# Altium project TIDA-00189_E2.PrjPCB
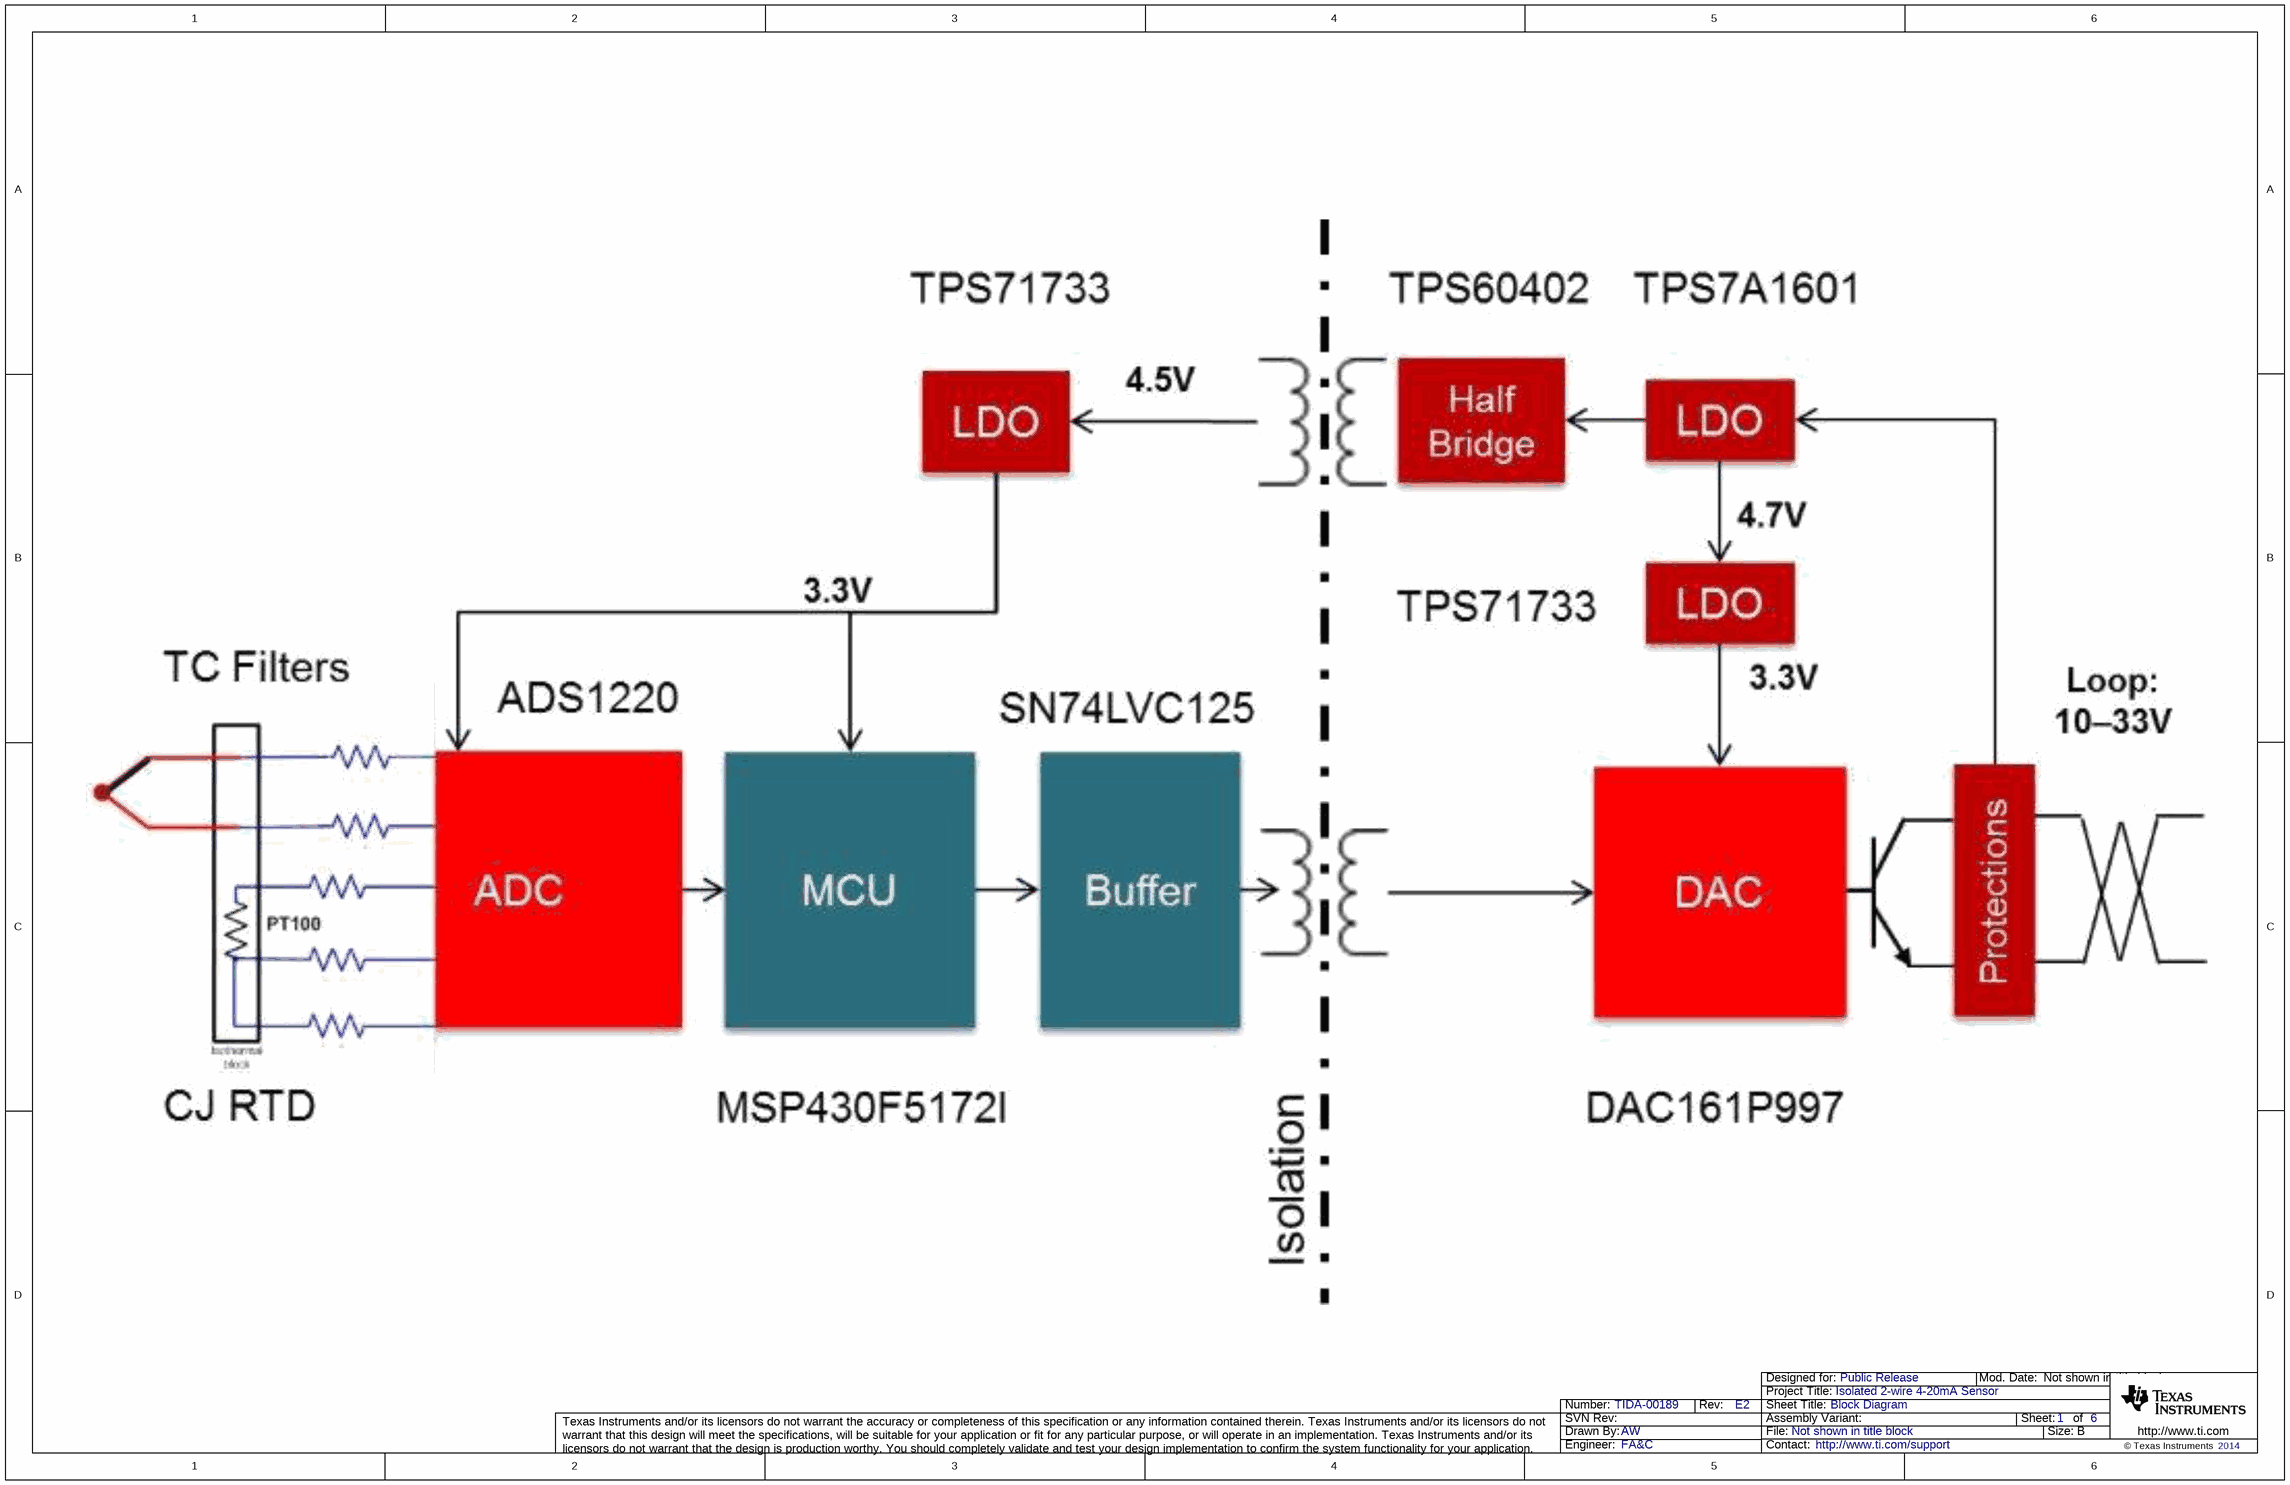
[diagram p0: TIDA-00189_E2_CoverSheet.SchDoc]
CopyrightYear: 2014; PCB_Layout: Jason M. Krypton Sol.; PCB_Rev: E1; PRJ_Customer: Public Release; PRJ_Engineer: FA&C; PRJ_Number: TIDA-00189; PRJ_Title: Isolated 2-wire 4-20mA Sensor; SCH_Rev: E2; TechSupport: http://www.ti.com/support
6 sheets, 164 parts. Net scope: global (net labels, ports and power ports of the same name join across sheets).
Board file: TIDA-00189_E2.PcbDoc
Sheets:
  TIDA-00189_E2_CoverSheet.SchDoc
  TIDA-00189_E2_Hardware.SchDoc
  TIDA-00189_E2_PWR.SchDoc
  TIDA-00189_E2_DAC.SchDoc
  TIDA-00189_E2_AFE_MCU.SchDoc
  TIDA-00189_E2_Periph.SchDoc

## Sheet TIDA-00189_E2_CoverSheet.SchDoc: Block Diagram
size 431 x 279 mm; Date: Not shown in title block; ApprovedBy: Not shown in title block; CheckedBy: Not shown in title block; Author: Not shown in title block; CompanyName: Not shown in title block; DrawnBy: AW; Engineer: Not shown in title block; Organization: Not shown in title block; Address1: Not shown in title block; Address2: Not shown in title block; Address3: Not shown in title block; Address4: Not shown in title block; DocumentNumber: 1; Revision: Use project parameter SCH_Rev; SheetNumber: 1; SheetTotal: 6; PageSetup: Record=PageOptions|CenterHorizontal=True|CenterVertical=True|PrintScale=1.00|XCorrection=1.00|YCorrection=1.00|PrintKind=0|BorderSize=5000000|LeftOffset=0|BottomOffset=0|Orientation=2|PaperLength=1000|PaperWidth=1000|Scale=100|PaperSource=15|PrintQuality=600|MediaType=1|DitherType=10|PaperKind=Letter|PrintScaleMode=1

## Sheet TIDA-00189_E2_Hardware.SchDoc: Hardware
size 431 x 279 mm; Date: Not shown in title block; ApprovedBy: Not shown in title block; CheckedBy: Not shown in title block; Author: Not shown in title block; CompanyName: Not shown in title block; DrawnBy: AW; Engineer: Not shown in title block; Organization: Not shown in title block; Address1: Not shown in title block; Address2: Not shown in title block; Address3: Not shown in title block; Address4: Not shown in title block; DocumentNumber: 2; Revision: Use project parameter SCH_Rev; SheetNumber: 2; SheetTotal: 6; PageSetup: Record=PageOptions|CenterHorizontal=True|CenterVertical=True|PrintScale=1.00|XCorrection=1.00|YCorrection=1.00|PrintKind=0|BorderSize=5000000|LeftOffset=0|BottomOffset=0|Orientation=2|PaperLength=1000|PaperWidth=1000|Scale=100|PaperSource=15|PrintQuality=600|MediaType=1|DitherType=10|PaperKind=Letter|PrintScaleMode=1
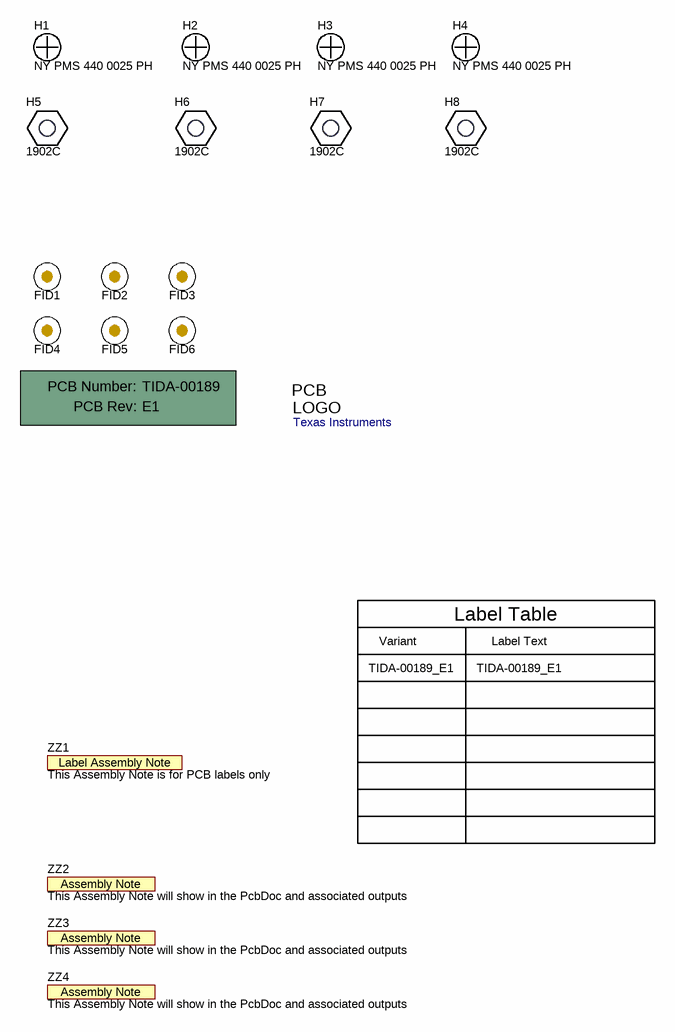
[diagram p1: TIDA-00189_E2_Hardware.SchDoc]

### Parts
!PCB1  Printed Circuit Board  (value not drawn)  (mechanical)
FID1  Fiducial  [Fiducial10-30]  (value not drawn)
FID2  Fiducial  [Fiducial10-30]  (value not drawn)
FID3  Fiducial  [Fiducial10-30]  (value not drawn)
FID4  Fiducial  [Fiducial10-30]  (value not drawn)
FID5  Fiducial  [Fiducial10-30]  (value not drawn)
FID6  Fiducial  [Fiducial10-30]  (value not drawn)
H1  NY PMS 440 0025 PH  [NY PMS 440 0025 PH]
H2  NY PMS 440 0025 PH  [NY PMS 440 0025 PH]
H3  NY PMS 440 0025 PH  [NY PMS 440 0025 PH]
H4  NY PMS 440 0025 PH  [NY PMS 440 0025 PH]
H5  1902C  [Keystone_1902C]
H6  1902C  [Keystone_1902C]
H7  1902C  [Keystone_1902C]
H8  1902C  [Keystone_1902C]
Logo1  Texas Instruments  [TI_Horizontal_Overlay_Small]  (no BOM)
ZZ1  This Assembly Note is for PCB labels only  [AssemblyNoteLabel]  (no BOM)
ZZ2  This Assembly Note will show in the PcbDoc and associated outputs  [AssemblyNote]  (no BOM)
ZZ3  This Assembly Note will show in the PcbDoc and associated outputs  [AssemblyNote]  (no BOM)
ZZ4  This Assembly Note will show in the PcbDoc and associated outputs  [AssemblyNote]  (no BOM)

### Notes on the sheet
- Variant
- Label Table
- Label Text
- TIDA-00189_E1

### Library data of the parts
!PCB1 = PCB: Manufacturer: Any; PartNumber: TIDA-00189; SymbolCreator: a0412235
FID1-FID6 = Fiducial: Fiducial mark.  There is nothing to buy or mount.; SymbolCreator: codlsc
H1-H4 = NY PMS 440 0025 PH: Machine Screw, Round, #4-40 x 1/4, Nylon, Philips panhead; Manufacturer: B&F Fastener Supply; CompType: Hardware; SymbolCreator: codlsc; U/M: EA
H5-H8 = 1902C: Standoff, Hex, 0.5"L #4-40 Nylon; Manufacturer: Keystone; CompType: Hardware; SymbolCreator: a0412235
Logo1 = TI_Logo: Texas Instrument Corporate Signature; SymbolCreator: a0412235
ZZ1 = AssemblyNoteLabel: SymbolCreator: a0412235
ZZ2-ZZ4 = AssemblyNote: SymbolCreator: codlsc

## Sheet TIDA-00189_E2_PWR.SchDoc: Power Supply & Protection
size 431 x 279 mm; Date: Not shown in title block; ApprovedBy: Not shown in title block; CheckedBy: Not shown in title block; Author: Not shown in title block; CompanyName: Not shown in title block; DrawnBy: AW; Engineer: Not shown in title block; Organization: Not shown in title block; Address1: Not shown in title block; Address2: Not shown in title block; Address3: Not shown in title block; Address4: Not shown in title block; DocumentNumber: 3; Revision: Use project parameter SCH_Rev; SheetNumber: 3; SheetTotal: 6; PageSetup: Record=PageOptions|CenterHorizontal=True|CenterVertical=True|PrintScale=0.94|XCorrection=1.00|YCorrection=1.00|PrintKind=0|BorderSize=5000000|LeftOffset=0|BottomOffset=0|Orientation=2|PaperLength=4200|PaperWidth=2970|Scale=100|PaperSource=7|PrintQuality=600|MediaType=1|DitherType=10|PaperKind=A3|PrintScaleMode=1
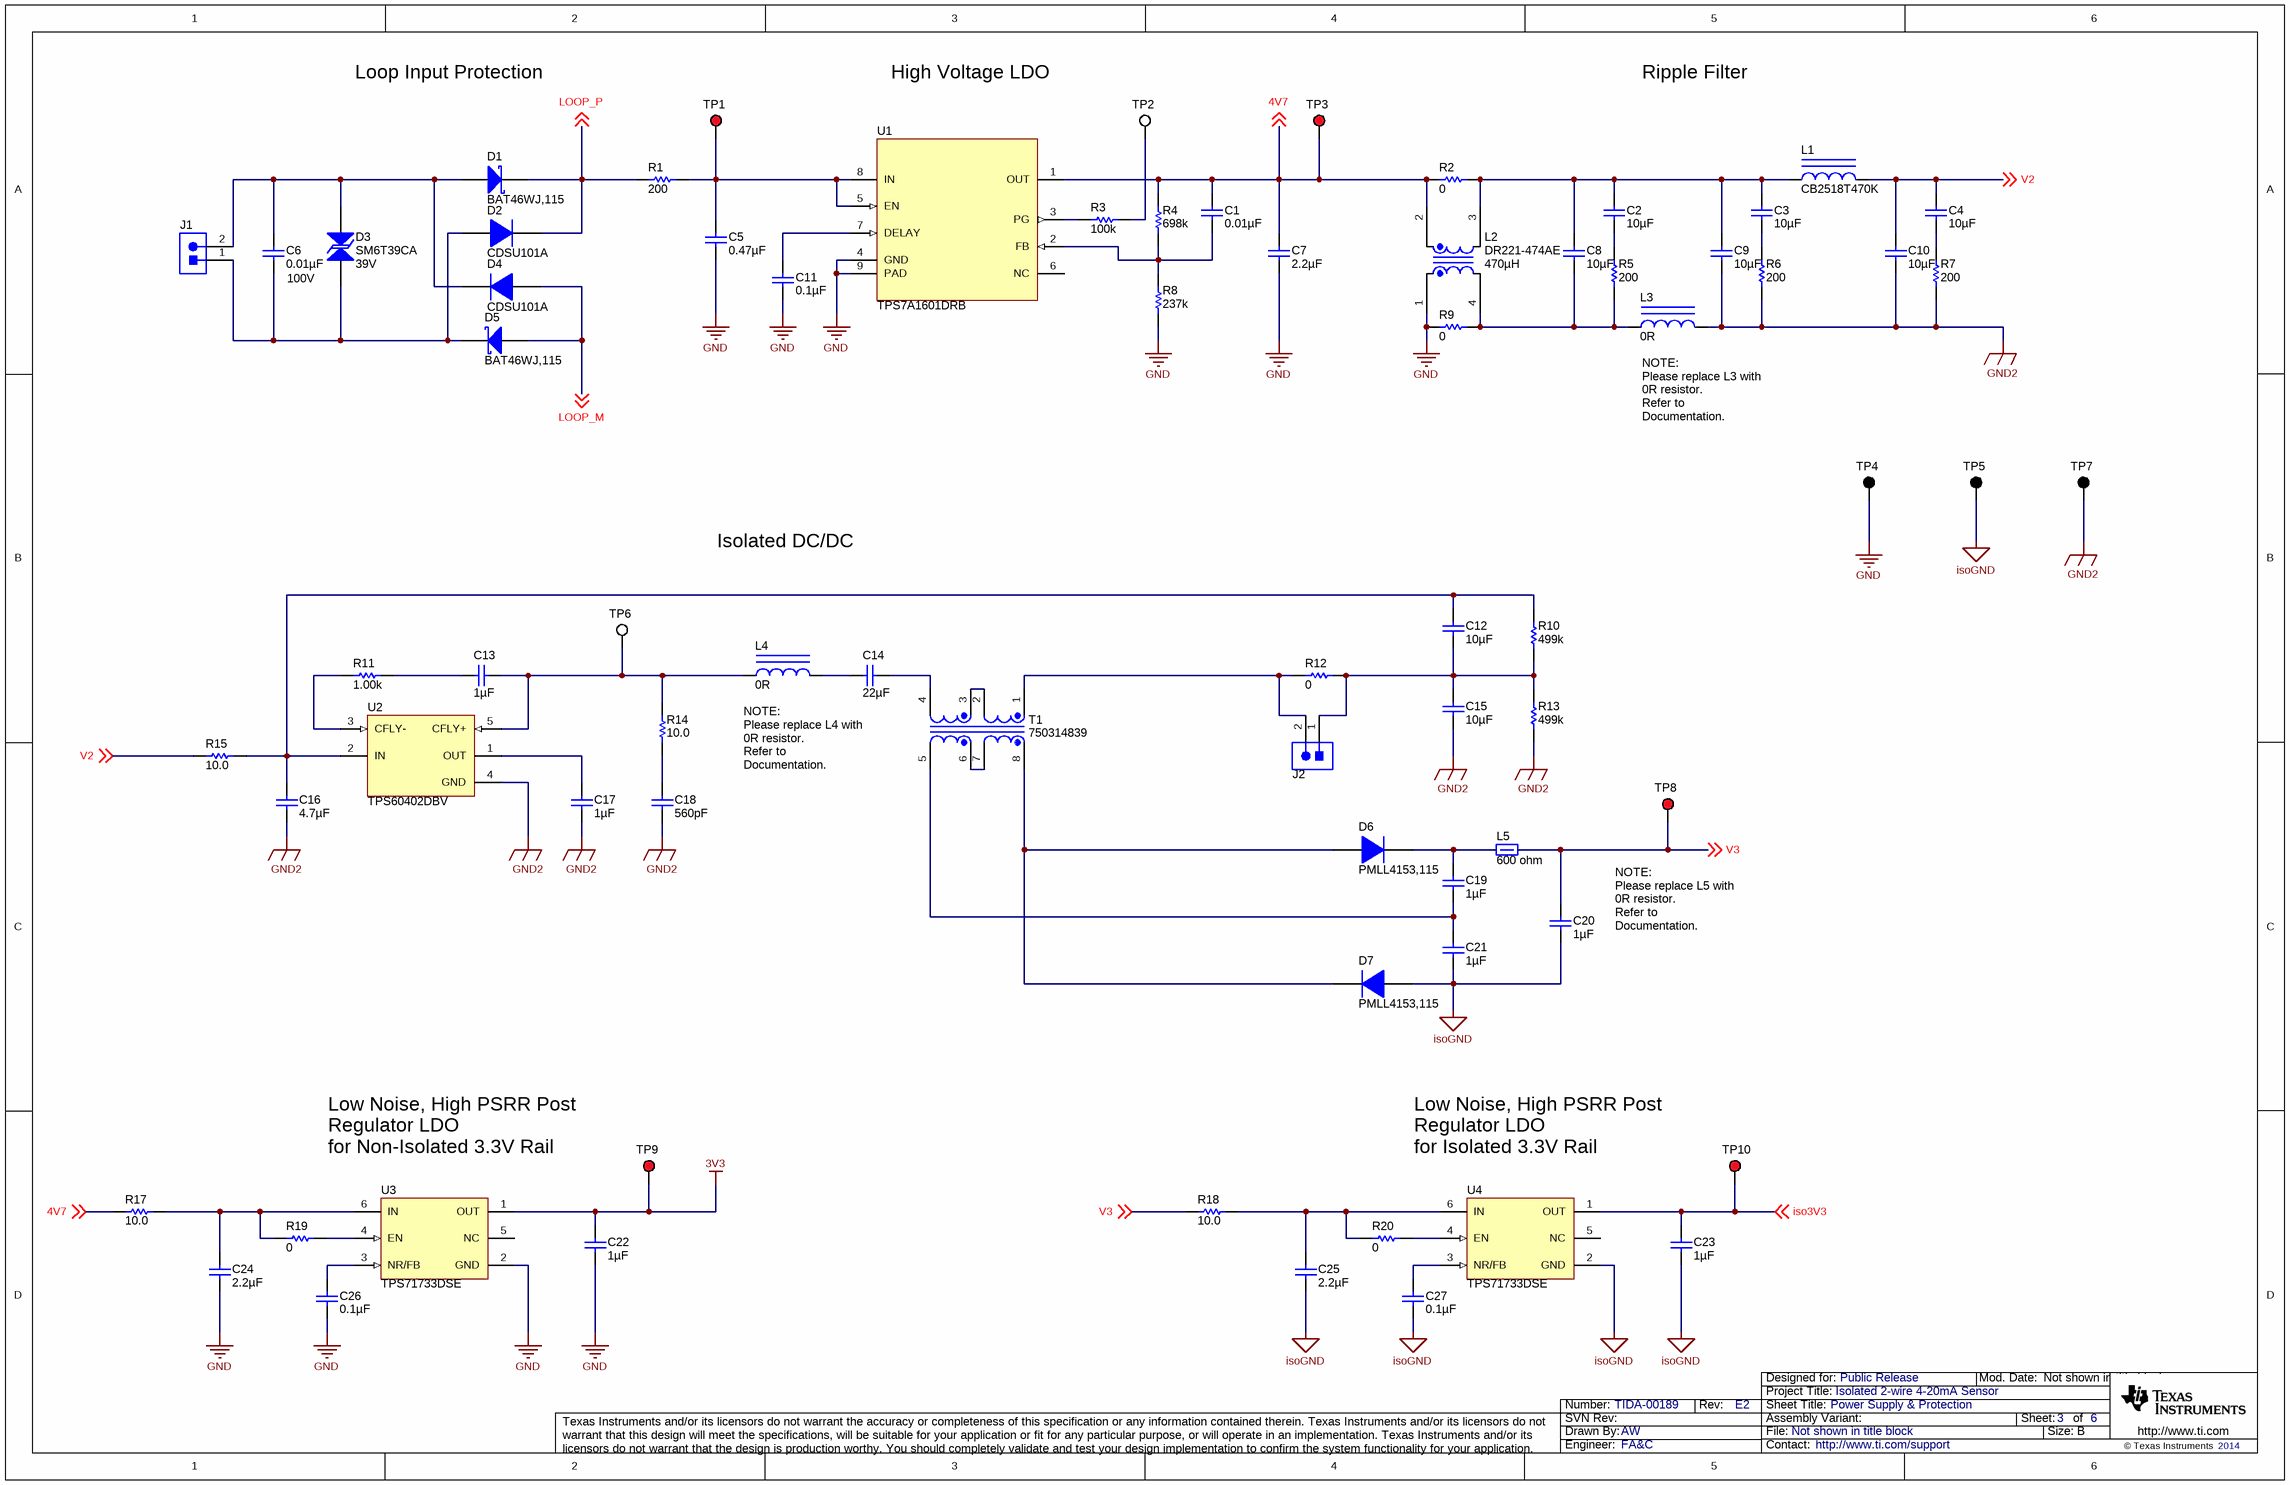
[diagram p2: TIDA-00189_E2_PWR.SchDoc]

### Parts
C1  ValueDisplayed: 0.01µF  [0402]  (hidden comment: CAP, CERM, 0.01uF, 10V, +/-10%, X5R, 0402)
C2  ValueDisplayed: 10µF  [0805]  (hidden comment: GRM21BR71A106KE51L)
C3  ValueDisplayed: 10µF  [0805]  (hidden comment: GRM21BR71A106KE51L)
C4  ValueDisplayed: 10µF  [0805]  (hidden comment: GRM21BR71A106KE51L)
C5  ValueDisplayed: 0.47µF  [0805]  (hidden comment: CAP, CERM, 0.47uF, 100V, +/-10%, X7R, 0805)
C6  ValueDisplayed: 0.01µF  Value2: 100V  [0603]  (hidden comment: CAP, CERM, 0.01uF, 100V, +/-10%, X7R, 0603)
C7  ValueDisplayed: 2.2µF  [0402]  (hidden comment: CAP, CERM, 2.2uF, 16V, +/-10%, X5R, 0402)
C8  ValueDisplayed: 10µF  [0805]  (hidden comment: CAP, CERM, 10uF, 10V, +/-10%, X7R, 0805)
C9  ValueDisplayed: 10µF  [0805]  (hidden comment: GRM21BR71A106KE51L)
C10  ValueDisplayed: 10µF  [0805]  (hidden comment: GRM21BR71A106KE51L)
C11  ValueDisplayed: 0.1µF  [0402]  (hidden comment: GRM155R61A104KA01D)
C12  ValueDisplayed: 10µF  [0805]  (hidden comment: CAP, CERM, 10uF, 10V, +/-10%, X7R, 0805)
C13  ValueDisplayed: 1µF  [0402]  (hidden comment: CAP, CERM, 1uF, 10V, +/-10%, X5R, 0402)
C14  ValueDisplayed: 22µF  [1206]  (hidden comment: CAP, CERM, 22uF, 10V, +/-10%, X5R, 1206)
C15  ValueDisplayed: 10µF  [0805]  (hidden comment: CAP, CERM, 10uF, 10V, +/-10%, X7R, 0805)
C16  ValueDisplayed: 4.7µF  [0402S]  (hidden comment: CAP, CERM, 4.7uF, 10V, +/-20%, X5R, 0402)
C17  ValueDisplayed: 1µF  [0402S]  (hidden comment: GRM155R61A105KE15D)
C18  ValueDisplayed: 560pF  [0402]  (hidden comment: GRM155R71H561KA01D)
C19  ValueDisplayed: 1µF  [0402S]  (hidden comment: CAP, CERM, 1uF, 10V, +/-10%, X5R, 0402)
C20  ValueDisplayed: 1µF  [0402S]  (hidden comment: CAP, CERM, 1uF, 10V, +/-10%, X5R, 0402)
C21  ValueDisplayed: 1µF  [0402S]  (hidden comment: CAP, CERM, 1uF, 10V, +/-10%, X5R, 0402)
C22  ValueDisplayed: 1µF  [0402]  (hidden comment: CAP, CERM, 1uF, 10V, +/-10%, X5R, 0402)
C23  ValueDisplayed: 1µF  [0402]  (hidden comment: GRM155R61A105KE15D)
C24  ValueDisplayed: 2.2µF  [0603]  (hidden comment: GRM188R71A225KE15D)
C25  ValueDisplayed: 2.2µF  [0603]  (hidden comment: GRM188R71A225KE15D)
C26  ValueDisplayed: 0.1µF  [0402]  (hidden comment: CAP, CERM, 0.1uF, 6.3V, +/-10%, X7R, 0402)
C27  ValueDisplayed: 0.1µF  [0402]  (hidden comment: GRM155R70J104KA01D)
D1  BAT46WJ,115  [SOD-323F]
D2  CDSU101A  [SOD-523F]
D3  SM6T39CA  value 39V  [SMB]
D4  CDSU101A  [SOD-523F]
D5  BAT46WJ,115  [SOD-323F]
D6  PMLL4153,115  [SOD-80]
D7  PMLL4153,115  [SOD-80]
J1  ED555/2DS  [TERM_BLK_ED555-2DS]  (value not drawn)
J2  90120-0122  [CONN_90120-0122]  (value not drawn)
L1  CB2518T470K  [IND_CB2518]
L2  DR221-474AE  ValueDisplayed: 470µH  [Bourns_DR221]
L3  0R  [IND_CB2518]
L4  0R  [IND_CB2518]
L5  value 600 ohm  [0603]  (hidden comment: 0R)
R1  value 200  [1206]  (hidden comment: CRCW1206200RFKEA)
R2  value 0  [0805_HV]  (hidden comment: CRCW08050000Z0EA)
R3  value 100k  [0402]  (hidden comment: CRCW0402100KFKED)
R4  value 698k  [0402]  (hidden comment: RES, 698k ohm, 1%, 0.063W, 0402)
R5  value 200  [0402]  (hidden comment: RES, 200 ohm, 1%, 0.063W, 0402)
R6  value 200  [0402]  (hidden comment: CRCW0402200RFKED)
R7  value 200  [0402]  (hidden comment: CRCW0402200RFKED)
R8  value 237k  [0402]  (hidden comment: RES, 237k ohm, 1%, 0.063W, 0402)
R9  value 0  [0805_HV]  (hidden comment: CRCW08050000Z0EA)
R10  value 499k  [0402]  (hidden comment: RES, 499k ohm, 1%, 0.063W, 0402)
R11  value 1.00k  [0402S]  (hidden comment: RES, 1.00k ohm, 1%, 0.063W, 0402)
R12  value 0  [0603]  (hidden comment: CRCW06030000Z0EA)
R13  value 499k  [0402]  (hidden comment: RES, 499k ohm, 1%, 0.063W, 0402)
R14  value 10.0  [0402]  (hidden comment: RES, 10.0 ohm, 1%, 0.063W, 0402)
R15  value 10.0  [0603]  (hidden comment: CRCW060310R0FKEA)
R17  value 10.0  [0603]  (hidden comment: CRCW060310R0FKEA)
R18  value 10.0  [0603]  (hidden comment: CRCW060310R0FKEA)
R19  value 0  [0402]  (hidden comment: RES, 0 ohm, 5%, 0.063W, 0402)
R20  value 0  [0402]  (hidden comment: CRCW04020000Z0ED)
T1  750314839  [Wurth_750314445]
TP1  5000  [Keystone5000]  (value not drawn)
TP2  5002  [Keystone5002]  (value not drawn)
TP3  5000  [Keystone5000]  (value not drawn)
TP4  5001  [Keystone5001]  (value not drawn)
TP5  5001  [Keystone5001]  (value not drawn)
TP6  5002  [Keystone5002]  (value not drawn)
TP7  5001  [Keystone5001]  (value not drawn)
TP8  5000  [Keystone5000]  (value not drawn)
TP9  5000  [Keystone5000]  (value not drawn)
TP10  5000  [Keystone5000]  (value not drawn)
U1  TPS7A1601DRB  [DRB0008A]
U2  TPS60402DBV  [DBV0005A_N]
U3  TPS71733DSE  [DSE0006A]
U4  TPS71733DSE  [DSE0006A]

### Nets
3V3: C22.1 TP9.1 U3.1(OUT)
GND: C5.2 C7.2 C11.2 C22.2 C24.2 C26.2 L2.1 R8.1 R9.1 TP4.1 U1.4(GND) U1.9(PAD) U3.2(GND)
GND2: C9.2 C10.2 C15.2 C16.2 C17.2 C18.2 L3.2 R6.1 R7.1 R13.1 TP7.1 U2.4(GND)
isoGND: C20.2 C21.2 C23.2 C25.2 C27.2 D7.2(A) TP5.1 U4.2(GND)
4V7: C1.1 C7.1 L2.2 R2.1 R4.2 R17.1 TP3.1 U1.1(OUT) ; off-sheet 4V7
iso3V3: C23.1 TP10.1 U4.1(OUT) ; off-sheet iso3V3
LOOP_M: D4.2(A) D5.2(A) ; off-sheet LOOP_M
LOOP_P: D1.1(K) D2.1(K) R1.1 ; off-sheet LOOP_P
V2: C4.1 C10.1 L1.2 R15.1 ; off-sheet V2
V3: C20.1 L5.2 R18.1 TP8.1 ; off-sheet V3
NetC1_2: C1.2 R4.1 R8.2 U1.2(FB)
NetC2_1: C2.1 C3.1 C8.1 C9.1 L1.1 L2.3 R2.2
NetC2_2: C2.2 R5.2
NetC3_2: C3.2 R6.2
NetC4_2: C4.2 R7.2
NetC5_1: C5.1 R1.2 TP1.1 U1.5(EN) U1.8(IN)
NetC6_1: C6.1 D1.2(A) D3.2 D4.1(K) J1.2
NetC6_2: C6.2 D2.2(A) D3.1 D5.1(K) J1.1
NetC8_2: C8.2 L2.4 L3.1 R5.1 R9.2
NetC11_1: C11.1 U1.7(DELAY)
NetC12_1: C12.1 C16.1 R10.2 R15.2 U2.2(IN)
NetC12_2: C12.2 C15.1 J2.1 R10.1 R12.2 R13.2
NetC13_1: C13.1 R11.2
NetC13_2: C13.2 L4.1 R14.2 TP6.1 U2.5(CFLY+)
NetC14_1: C14.1 T1.4
NetC14_2: C14.2 L4.2
NetC17_1: C17.1 U2.1(OUT)
NetC18_1: C18.1 R14.1
NetC19_1: C19.1 D6.1(K) L5.1
NetC19_2: C19.2 C21.1 T1.5
NetC24_1: C24.1 R17.2 R19.2 U3.6(IN)
NetC25_1: C25.1 R18.2 R20.2 U4.6(IN)
NetC26_1: C26.1 U3.3(NR/FB)
NetC27_1: C27.1 U4.3(NR/FB)
NetD6_2: D6.2(A) D7.1(K) T1.8
NetJ2_2: J2.2 R12.1 T1.1
NetR3_1: R3.1 U1.3(PG)
NetR3_2: R3.2 TP2.1
NetR11_1: R11.1 U2.3(CFLY-)
NetR19_1: R19.1 U3.4(EN)
NetR20_1: R20.1 U4.4(EN)
NetT1_2: T1.2 T1.3
NetT1_6: T1.6 T1.7

Not connected (* = marked no-connect by the designer): U1 6(NC); U3 5(NC); U4 5(NC)

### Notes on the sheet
- Loop Input Protection
- (near TP2) High Voltage LDO
- Ripple Filter
- (near L3) NOTE:
  Please replace L3 with 0R resistor.
  Refer to Documentation.
- Isolated DC/DC Converter
- NOTE:
  Please replace L4 with 0R resistor.
  Refer to Documentation.
- NOTE:
  Please replace L5 with 0R resistor.
  Refer to Documentation.
- Low Noise, High PSRR Post  Regulator LDO
  for Non-Isolated 3.3V Rail
- Low Noise, High PSRR Post  Regulator LDO
  for Isolated 3.3V Rail

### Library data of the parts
C1 = GRM155R61A103KA01D: Manufacturer: MuRata; Polarized: N; CompType: Capacitor; U/M: EA; Cap_F: 0.00000001; Tolerance_%: 10; Value1: Unknown; TaMin_C: -55; TaMax_C: 85
C2-C4 C9 C10 = GRM21BR71A106KE51L: CAP, CERM, 10uF, 10V, +/-10%, X7R, 0805; Manufacturer: MuRata; Polarized: N; CompType: Capacitor; U/M: EA; Cap_F: 0.00001; Tolerance_%: 10; ESR_Ohm: 0.003; Value1: 0.003 ohm; TaMin_C: -55; TaMax_C: 125
C5 = GRM21BR72A474KA73L: Manufacturer: MuRata; Polarized: N; CompType: Capacitor; U/M: EA; Cap_F: 0.00000047; Tolerance_%: 10; Value1: Unknown; VDC_V: 100; TaMin_C: -55; TaMax_C: 125
C6 = GRM188R72A103KA01D: Manufacturer: MuRata; Polarized: N; CompType: Capacitor; U/M: EA; Cap_F: 0.00000001; Tolerance_%: 10; Value1: Unknown; VDC_V: 100; TaMin_C: -55; TaMax_C: 125
C7 = C1005X5R1C225K050BC: Manufacturer: TDK; Polarized: N; CompType: Capacitor; U/M: EA; Cap_F: 0.0000022; Tolerance_%: 10; Value1: Unknown; VDC_V: 16; TaMin_C: -55; TaMax_C: 85
C8 C12 C15 = GRM21BR71A106KE51L: Manufacturer: MuRata; Polarized: N; CompType: Capacitor; U/M: EA; Cap_F: 0.00001; Tolerance_%: 10; ESR_Ohm: 0.003; Value1: 0.003 ohm; TaMin_C: -55; TaMax_C: 125
C11 = GRM155R61A104KA01D: CAP, CERM, 0.1uF, 10V, +/-10%, X5R, 0402; Manufacturer: MuRata; Polarized: N; CompType: Capacitor; U/M: EA; Cap_F: 0.0000001; Tolerance_%: 10; Value1: Unknown; TaMin_C: -55; TaMax_C: 85
C13 C22 = GRM155R61A105KE15D: Manufacturer: MuRata; Polarized: N; CompType: Capacitor; U/M: EA; Cap_F: 0.000001; Tolerance_%: 10; Value1: Unknown; TaMin_C: -55; TaMax_C: 85
C14 = GRM31CR61A226KE19L: Manufacturer: MuRata; Polarized: N; CompType: Capacitor; U/M: EA; Cap_F: 0.000022; Tolerance_%: 10; Value1: Unknown; TaMin_C: -55; TaMax_C: 85
C16 = GRM155R61A475M: Manufacturer: MuRata; Polarized: N; CompType: Capacitor; U/M: EA; Cap_F: 0.0000047; Tolerance_%: 20; Value1: Unknown; VDC_V: 10; TaMin_C: -55; TaMax_C: 85; Cap_Case: 0402
C17 = GRM155R61A105KE15D: CAP, CERM, 1uF, 10V, +/-10%, X5R, 0402; Manufacturer: MuRata; Polarized: N; CompType: Capacitor; U/M: EA; Cap_F: 0.000001; Tolerance_%: 10; Value1: Unknown; TaMin_C: -55; TaMax_C: 85; Cap_Case: 0402
C18 = GRM155R71H561KA01D: CAP, CERM, 560pF, 50V, +/-10%, X7R, 0402; Manufacturer: MuRata; Polarized: N; CompType: Capacitor; U/M: EA; Cap_F: 0.00000000056; Tolerance_%: 10; Value1: Unknown; VDC_V: 50; TaMin_C: -55; TaMax_C: 125
C19-C21 = GRM155R61A105KE15D: Manufacturer: MuRata; Polarized: N; CompType: Capacitor; U/M: EA; Cap_F: 0.000001; Tolerance_%: 10; Value1: Unknown; TaMin_C: -55; TaMax_C: 85; Cap_Case: 0402
C23 = GRM155R61A105KE15D: CAP, CERM, 1uF, 10V, +/-10%, X5R, 0402; Manufacturer: MuRata; Polarized: N; CompType: Capacitor; U/M: EA; Cap_F: 0.000001; Tolerance_%: 10; Value1: Unknown; TaMin_C: -55; TaMax_C: 85
C24 C25 = GRM188R71A225KE15D: CAP, CERM, 2.2uF, 10V, +/-10%, X7R, 0603; Manufacturer: MuRata; Polarized: N; CompType: Capacitor; U/M: EA; Cap_F: 0.0000022; Tolerance_%: 10; ESR_Ohm: 0.009; Value1: 0.009 ohm; TaMin_C: -55; TaMax_C: 125
C26 = GRM155R70J104KA01D: Manufacturer: MuRata; Polarized: N; CompType: Capacitor; U/M: EA; Cap_F: 0.0000001; Tolerance_%: 10; Value1: Unknown; VDC_V: 6.3; TaMin_C: -55; TaMax_C: 125
C27 = GRM155R70J104KA01D: CAP, CERM, 0.1uF, 6.3V, +/-10%, X7R, 0402; Manufacturer: MuRata; Polarized: N; CompType: Capacitor; U/M: EA; Cap_F: 0.0000001; Tolerance_%: 10; Value1: Unknown; VDC_V: 6.3; TaMin_C: -55; TaMax_C: 125
D1 D5 = BAT46WJ,115: Diode, Schottky, 100V, 0.25A, SOD-323F; Manufacturer: NXP Semiconductor; U/M: EA; Vf_V: 0.85; Value2: 0.85V; Io_A: 0.25; Vr_V: 100; TJmax_C: 150
D2 D4 = CDSU101A: Diode, Switching, 90V, 0.1A, SOD-523F; Manufacturer: Comchip Technology; U/M: EA; Vf_V: 1; Value2: 1V; Io_A: 0.1; Vr_V: 90; TJmax_C: 125
D3 = SM6T39CA: Diode, TVS, Bi, 39V, 600W, SMB; Manufacturer: ST Microelectronics; U/M: EA; Power_W: 600; Vr_V: 39; RJA_CperW: 100
D6 D7 = PMLL4153,115: Diode, Fast Rectifier, 75V, 0.2A, 3.7x1.6x1.6mm; Manufacturer: NXP Semiconductor; U/M: EA; Value2: V; Io_A: 0.2; Vr_V: 75; TJmax_C: 200
J1 = ED555/2DS: Terminal Block, 6A, 3.5mm Pitch, 2-Pos, TH; Manufacturer: On-Shore Technology; SymbolCreator: a0412235; CompType: Connector; U/M: EA
J2 = 90120-0122: Header, 100mil, 2x1, Tin plated, TH; Manufacturer: Molex; SymbolCreator: a0412235; U/M: EA
L1 L3 = CB2518T470K: Inductor, Wirewound, Ferrite, 47uH, 0.11A, 1.235 ohm, SMD; Manufacturer: Taiyo Yuden; Ind_H: 47.0E-6; ValueDisplayed: 47µH; Imax_A: 0.11; Irms: 0.42A @ 40C rise; Isat: 0.11A @ 30% inductance drop; DCR_ohm: 1.235
L2 = DR221-474AE: Coupled inductor, 470uH, 0.1A, 0.35 ohm, +/-30%, SMD; Manufacturer: Bourns; SymbolCreator: a0799628; Ind_H: 470.0E-6; DCR_ohm: 0.35; Isat: 0.1; Tolerance_%: 30
L4 = CB2518T330K: Inductor, Wirewound, Ferrite, 33uH, 0.13A, 0.7 ohm, SMD; Manufacturer: Taiyo Yuden; Ind_H: 33.0E-6; ValueDisplayed: 33µH; Imax_A: 0.13; Irms: 0.46A @ 40C rise; Isat: 0.13A @ 30% inductance drop; DCR_ohm: 0.7; Value1: 0.7 ohm
L5 = BLM18HG601SN1D: Ferrite Bead, 600 ohm @ 100MHz, 0.2A, 0603; Manufacturer: MuRata; Imax_A: 0.2; DCR_ohm: 1; Value1: 1 ohm; ZTyp@100MHz_Ohm: 600; Ztyp@1GHz_Ohm: 700
R1 = CRCW1206200RFKEA: RES, 200 ohm, 1%, 0.25W, 1206; Manufacturer: Vishay-Dale; CompType: Resistor; Value_Code: 200R; Tolerance_%: 1; Power_W: 0.25; TempCo: 100 ppm/C; EIA_Code: E96; U/M: EA
R2 R9 = CRCW08050000Z0EA: RES, 0 ohm, 5%, 0.125W, 0805; Manufacturer: Vishay-Dale; CompType: Resistor; Value_Code: 0000; Tolerance_%: 5; Power_W: 0.125; VDC_V: 150; TempCo: 200 ppm/C; EIA_Code: E24; U/M: EA
R3 = CRCW0402100KFKED: RES, 100k ohm, 1%, 0.063W, 0402; Manufacturer: Vishay-Dale; CompType: Resistor; Res_ohm: 100000; Tolerance_%: 1; Power_W: 0.063; VDC_V: 50; TempCo: 100 ppm/C; EIA_Code: E96; U/M: EA
R4 = CRCW0402698KFKED: Manufacturer: Vishay-Dale; CompType: Resistor; Res_ohm: 698000; Tolerance_%: 1; Power_W: 0.063; VDC_V: 50; TempCo: 100 ppm/C; EIA_Code: E96; U/M: EA
R5 = CRCW0402200RFKED: Manufacturer: Vishay-Dale; CompType: Resistor; Value_Code: 200R; Tolerance_%: 1; Power_W: 0.063; VDC_V: 50; TempCo: 100 ppm/C; EIA_Code: E96; U/M: EA
R6 R7 = CRCW0402200RFKED: RES, 200 ohm, 1%, 0.063W, 0402; Manufacturer: Vishay-Dale; CompType: Resistor; Value_Code: 200R; Tolerance_%: 1; Power_W: 0.063; VDC_V: 50; TempCo: 100 ppm/C; EIA_Code: E96; U/M: EA
R8 = CRCW0402237KFKED: Manufacturer: Vishay-Dale; CompType: Resistor; Res_ohm: 237000; Tolerance_%: 1; Power_W: 0.063; VDC_V: 50; TempCo: 100 ppm/C; EIA_Code: E96; U/M: EA
R10 R13 = CRCW0402499KFKED: Manufacturer: Vishay-Dale; CompType: Resistor; Res_ohm: 499000; Tolerance_%: 1; Power_W: 0.063; VDC_V: 50; TempCo: 100 ppm/C; EIA_Code: E96; U/M: EA
R11 = CRCW04021K00FKED: Manufacturer: Vishay-Dale; CompType: Resistor; Res_ohm: 1000; Value_Code: 1k00; Tolerance_%: 1; Power_W: 0.063; VDC_V: 50; TempCo: 100 ppm/C; EIA_Code: E96; U/M: EA
R12 = CRCW06030000Z0EA: RES, 0 ohm, 5%, 0.1W, 0603; Manufacturer: Vishay-Dale; CompType: Resistor; Value_Code: 0000; Tolerance_%: 5; Power_W: 0.1; VDC_V: 75; TempCo: 200 ppm/C; EIA_Code: E24; U/M: EA
R14 = CRCW040210R0FKED: Manufacturer: Vishay-Dale; CompType: Resistor; Res_ohm: 10; Value_Code: 10R0; Tolerance_%: 1; Power_W: 0.063; VDC_V: 50; TempCo: 100 ppm/C; EIA_Code: E96; U/M: EA
R15 R17 R18 = CRCW060310R0FKEA: RES, 10.0 ohm, 1%, 0.1W, 0603; Manufacturer: Vishay-Dale; CompType: Resistor; Res_ohm: 10; Value_Code: 10R0; Tolerance_%: 1; Power_W: 0.1; VDC_V: 75; TempCo: 100 ppm/C; EIA_Code: E96; U/M: EA
R19 = CRCW04020000Z0ED: Manufacturer: Vishay-Dale; CompType: Resistor; Value_Code: 0000; Tolerance_%: 5; Power_W: 0.063; VDC_V: 50; TempCo: 200 ppm/C; EIA_Code: E24; U/M: EA
R20 = CRCW04020000Z0ED: RES, 0 ohm, 5%, 0.063W, 0402; Manufacturer: Vishay-Dale; CompType: Resistor; Value_Code: 0000; Tolerance_%: 5; Power_W: 0.063; VDC_V: 50; TempCo: 200 ppm/C; EIA_Code: E24; U/M: EA
T1 = 750314839: Transformer, 3mH, SMT; Manufacturer: Wurth Elektronik eiSos; SymbolCreator: a0799628; DCR_Ohm: 1.2; U/M: EA
TP1 TP3 TP8-TP10 = 5000: Test Point, Miniature, Red, TH; Manufacturer: Keystone; CompType: Test Point Loop; U/M: EA
TP2 TP6 = 5002: Test Point, Miniature, White, TH; Manufacturer: Keystone; CompType: Test Point Loop; U/M: EA
TP4 TP5 TP7 = 5001: Test Point, Miniature, Black, TH; Manufacturer: Keystone; CompType: Test Point Loop; U/M: EA
U1 = TPS7A1601DRB: 60-V, 5-µA IQ, 100-mA, Low-Dropout Voltage Regulator with Enable and Power-Good, DRB0008A; Alternate Manufacturer: None; Manufacturer: Texas Instruments; SymbolCreator: a0411947; CompType: IC; U/M: EA
U2 = TPS60402DBV: UNREGULATED 60-mA CHARGE PUMP VOLTAGE INVERTER, DBV0005A; Alternate Manufacturer: None; Manufacturer: Texas Instruments; SymbolCreator: a0799628; CompType: IC; U/M: EA
U3 U4 = TPS71733DSE: Low Noise, High-Bandwidth PSRR Low-Dropout 150mA Linear Regulator, DSE0006A; Alternate Manufacturer: None; Manufacturer: Texas Instruments; SymbolCreator: a0411947; CompType: IC; U/M: EA

## Sheet TIDA-00189_E2_DAC.SchDoc: Loop Current - DAC
size 431 x 279 mm; Date: Not shown in title block; ApprovedBy: Not shown in title block; CheckedBy: Not shown in title block; Author: Not shown in title block; CompanyName: Not shown in title block; DrawnBy: AW; Engineer: Not shown in title block; Organization: Not shown in title block; Address1: Not shown in title block; Address2: Not shown in title block; Address3: Not shown in title block; Address4: Not shown in title block; DocumentNumber: 4; Revision: Use project parameter SCH_Rev; SheetNumber: 4; SheetTotal: 6; PageSetup: Record=PageOptions|CenterHorizontal=True|CenterVertical=True|PrintScale=0.94|XCorrection=1.00|YCorrection=1.00|PrintKind=0|BorderSize=5000000|LeftOffset=0|BottomOffset=0|Orientation=2|PaperLength=4200|PaperWidth=2970|Scale=100|PaperSource=7|PrintQuality=600|MediaType=1|DitherType=10|PaperKind=A3|PrintScaleMode=1
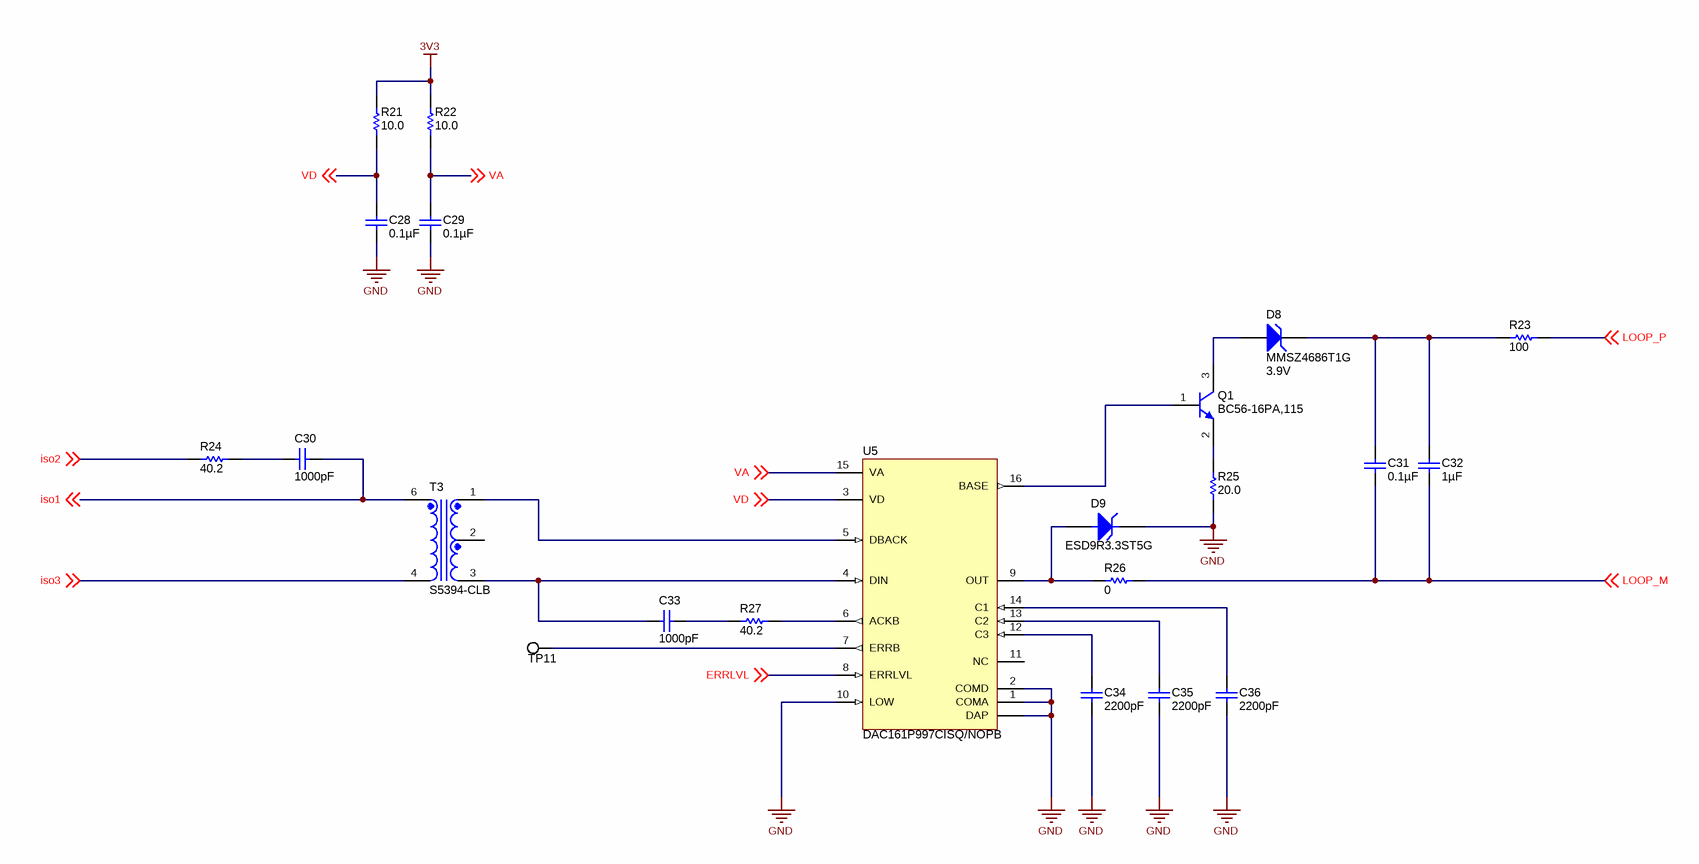
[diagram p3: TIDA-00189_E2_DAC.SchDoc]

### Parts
C28  ValueDisplayed: 0.1µF  [0402]  (hidden comment: GRM155R71C104KA88D)
C29  ValueDisplayed: 0.1µF  [0402]  (hidden comment: GRM155R71C104KA88D)
C30  ValueDisplayed: 1000pF  [0402S]  (hidden comment: GRM155R71C102KA01D)
C31  ValueDisplayed: 0.1µF  [1206]  (hidden comment: 12061C104JAT2A)
C32  ValueDisplayed: 1µF  [1206]  (hidden comment: GRM31CR72A105KA01L)
C33  ValueDisplayed: 1000pF  [0402S]  (hidden comment: GRM155R71C102KA01D)
C34  ValueDisplayed: 2200pF  [0402]  (hidden comment: GRM155R70J222KA01D)
C35  ValueDisplayed: 2200pF  [0402]  (hidden comment: GRM155R70J222KA01D)
C36  ValueDisplayed: 2200pF  [0402]  (hidden comment: GRM155R70J222KA01D)
D8  MMSZ4686T1G  value 3.9V  [SOD-123]
D9  ESD9R3.3ST5G  [ESD9R3.3ST5G]
Q1  BC56-16PA,115  [SOT1061]
R21  value 10.0  [0603]  (hidden comment: CRCW060310R0FKEA)
R22  value 10.0  [0603]  (hidden comment: CRCW060310R0FKEA)
R23  value 100  [0603]  (hidden comment: RT0603BRD07100RL)
R24  value 40.2  [0402S]  (hidden comment: CRCW040240R2FKED)
R25  value 20.0  [0603]  (hidden comment: CRCW060320R0FKEA)
R26  value 0  [1206]  (hidden comment: CRCW12060000Z0EA)
R27  value 40.2  [0402S]  (hidden comment: CRCW040240R2FKED)
T3  S5394-CLB  [Coilcraft_S5394-CL]
TP11  5002  [Keystone5002]  (value not drawn)
U5  DAC161P997CISQ/NOPB  [RGH0016A]

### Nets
3V3: R21.2 R22.2
GND: C28.2 C29.2 C34.2 C35.2 C36.2 D9.1(K) R25.1 U5.1(COMA) U5.2(COMD) U5.10(LOW) U5.17(DAP)
ERRLVL: U5.8(ERRLVL) ; off-sheet ERRLVL
iso1: C30.1 T3.6 ; off-sheet iso1
iso2: R24.1 ; off-sheet iso2
iso3: T3.4 ; off-sheet iso3
LOOP_M: C31.2 C32.2 R26.2 ; off-sheet LOOP_M
LOOP_P: R23.2 ; off-sheet LOOP_P
VA: C29.1 R22.1 U5.15(VA) ; off-sheet VA
VD: C28.1 R21.1 U5.3(VD) ; off-sheet VD
NetC30_2: C30.2 R24.2
NetC31_1: C31.1 C32.1 D8.1(K) R23.1
NetC33_1: C33.1 R27.1
NetC33_2: C33.2 T3.3 U5.4(DIN)
NetC34_1: C34.1 U5.12(C3)
NetC35_1: C35.1 U5.13(C2)
NetC36_1: C36.1 U5.14(C1)
NetD8_2: D8.2(A) Q1.3(C)
NetD9_2: D9.2(A) R26.1 U5.9(OUT)
NetQ1_1: Q1.1(B) U5.16(BASE)
NetQ1_2: Q1.2(E) R25.2
NetR27_2: R27.2 U5.6(ACKB)
NetT3_1: T3.1 U5.5(DBACK)
NetTP11_1: TP11.1 U5.7(ERRB)

Not connected (* = marked no-connect by the designer): T3 2; U5 11(NC)

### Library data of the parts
C28 C29 = GRM155R71C104KA88D: CAP, CERM, 0.1uF, 16V, +/-10%, X7R, 0402; Manufacturer: MuRata; Polarized: N; CompType: Capacitor; U/M: EA; Cap_F: 0.0000001; Tolerance_%: 10; Value1: Unknown; VDC_V: 16; TaMin_C: -55; TaMax_C: 125
C30 C33 = GRM155R71C102KA01D: CAP, CERM, 1000pF, 16V, +/-10%, X7R, 0402; Manufacturer: MuRata; Polarized: N; CompType: Capacitor; U/M: EA; Cap_F: 0.000000001; Tolerance_%: 10; Value1: Unknown; VDC_V: 16; TaMin_C: -55; TaMax_C: 125; Cap_Case: 0402
C31 = 12061C104JAT2A: CAP, CERM, 0.1uF, 100V, +/-5%, X7R, 1206; Manufacturer: AVX; Polarized: N; CompType: Capacitor; U/M: EA; Cap_F: 0.0000001; Tolerance_%: 5; ESR_Ohm: 0.037; Value1: 0.037 ohm; VDC_V: 100; TaMin_C: -55; TaMax_C: 125
C32 = GRM31CR72A105KA01L: CAP, CERM, 1uF, 100V, +/-10%, X7R, 1206; Manufacturer: MuRata; Polarized: N; CompType: Capacitor; U/M: EA; Cap_F: 0.000001; Tolerance_%: 10; Value1: Unknown; VDC_V: 100; TaMin_C: -55; TaMax_C: 125; Cap_Case: 2220
C34-C36 = GRM155R70J222KA01D: CAP, CERM, 2200pF, 6.3V, +/-10%, X7R, 0402; Manufacturer: MuRata; Polarized: N; CompType: Capacitor; U/M: EA; Cap_F: 0.0000000022; Tolerance_%: 10; Value1: Unknown; VDC_V: 6.3; TaMin_C: -55; TaMax_C: 125
D8 = MMSZ4686T1G: Diode, Zener, 3.9V, 500mW, SOD-123; Manufacturer: ON Semiconductor; SymbolCreator: a0412235; U/M: EA; Power_W: 0.5; Vz_V: 3.9; Value1: 0.5W; RJA_CperW: 340
D9 = ESD9R3.3ST5G: TVS DIODE 3.3VWM 7.8VC SOD923; Manufacturer: ON Semiconductor; Type: Zener; Unidirectional Channels: 1; Voltage - Reverse Standoff (Typ): 3.3V (Max); Voltage - Breakdown (Min): 4.8V; Voltage - Clamping (Max) @ Ipp: 7.8V; Current - Peak Pulse (10/1000µs): 1A (8/20µs); Power Line Protection: No; Capacitance @ Frequency: 0.5pF @ 1MHz
Q1 = BC56-16PA,115, NXP Semiconductor: Transistor, NPN, 80V, 1A, SOT1061; CompType: BJT; PNP: 0; NPN: 1; Vceo_V: 80; Value: V; HfeMax: 250; TaMin_C: -55; TaMax_C: 150; U/M: EA
R21 R22 = CRCW060310R0FKEA: as R15 on sheet TIDA-00189_E2_PWR
R23 = RT0603BRD07100RL: RES, 100 ohm, 0.1%, 0.1W, 0603; Manufacturer: Yageo America; CompType: Resistor; Value_Code: 100R; Tolerance_%: 0.1; VDC_V: 75; TempCo: 25 ppm/C; EIA_Code: E192; U/M: EA
R24 R27 = CRCW040240R2FKED: RES, 40.2 ohm, 1%, 0.063W, 0402; Manufacturer: Vishay-Dale; CompType: Resistor; Value_Code: 40R2; Tolerance_%: 1; Power_W: 0.063; VDC_V: 50; TempCo: 100 ppm/C; EIA_Code: E96; U/M: EA
R25 = CRCW060320R0FKEA: RES, 20.0 ohm, 1%, 0.1W, 0603; Manufacturer: Vishay-Dale; CompType: Resistor; Res_ohm: 20; Value_Code: 20R0; Tolerance_%: 1; Power_W: 0.1; VDC_V: 75; TempCo: 100 ppm/C; EIA_Code: E96; U/M: EA
R26 = CRCW12060000Z0EA: RES, 0 ohm, 5%, 0.25W, 1206; Manufacturer: Vishay-Dale; CompType: Resistor; Value_Code: 0000; Tolerance_%: 5; Power_W: 0.25; VDC_V: 200; TempCo: 200 ppm/C; EIA_Code: E24; U/M: EA
T3 = S5394-CLB: Transformer_400uH, SMT; Manufacturer: Coilcraft; SymbolCreator: a0411947; DCR_Ohm: 0.95; Value: 400uH; U/M: EA
TP11 = 5002: as TP2 on sheet TIDA-00189_E2_PWR
U5 = DAC161P997CISQ/NOPB: Single-Wire 16-bit DAC for 4-20mA loops, RGH0016A; Alternate Manufacturer: None; Manufacturer: Texas Instruments; SymbolCreator: x0208325; CompType: IC; U/M: EA

## Sheet TIDA-00189_E2_AFE_MCU.SchDoc: Analog Front-End, MCU & isolated data
size 431 x 279 mm; Date: Not shown in title block; ApprovedBy: Not shown in title block; CheckedBy: Not shown in title block; Author: Not shown in title block; CompanyName: Not shown in title block; DrawnBy: AW; Engineer: Not shown in title block; Organization: Not shown in title block; Address1: Not shown in title block; Address2: Not shown in title block; Address3: Not shown in title block; Address4: Not shown in title block; DocumentNumber: 5; Revision: Use project parameter SCH_Rev; SheetNumber: 5; SheetTotal: 6; PageSetup: Record=PageOptions¦CenterHorizontal=True¦CenterVertical=True¦PrintScale=0.94¦XCorrection=1.00¦YCorrection=1.00¦PrintKind=0¦BorderSize=5000000¦LeftOffset=0¦BottomOffset=0¦Orientation=2¦PaperLength=4200¦PaperWidth=2970¦Scale=100¦PaperSource=7¦PrintQuality=600¦MediaType=1¦DitherType=10¦PrintScaleMode=1¦PaperKind=A3
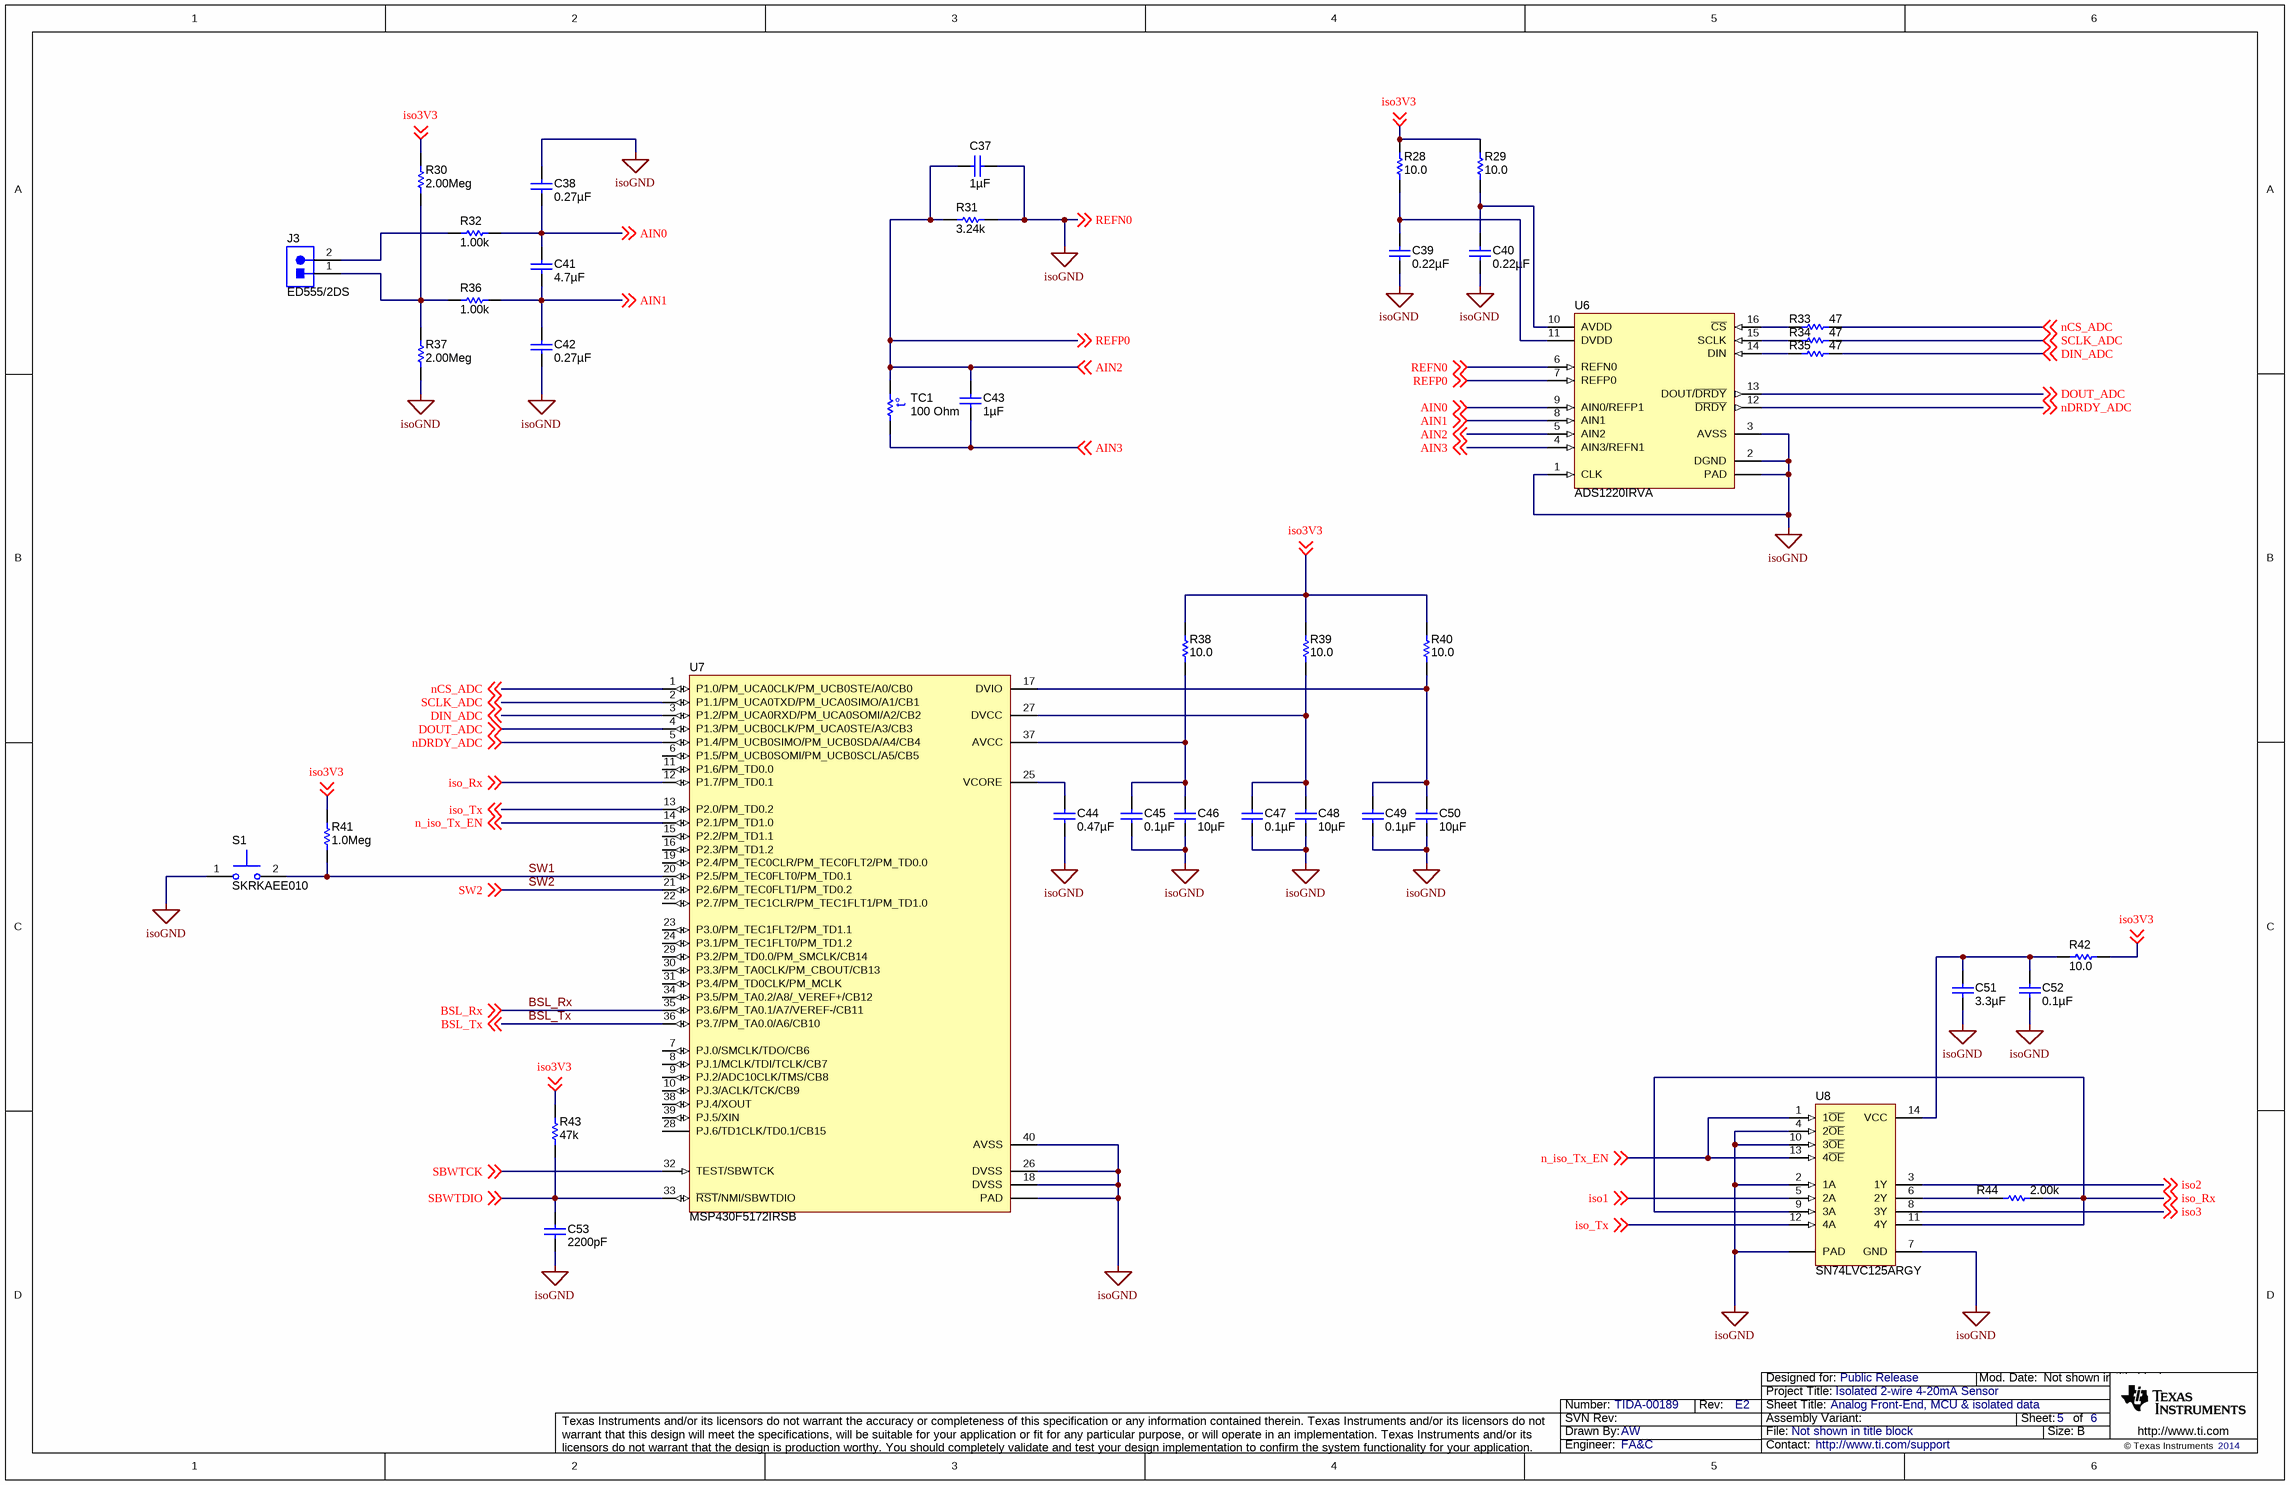
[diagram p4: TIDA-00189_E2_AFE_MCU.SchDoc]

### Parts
C37  ValueDisplayed: 1µF  [0402]  (hidden comment: GRM155R61A105KE15D)
C38  ValueDisplayed: 0.27µF  [0402]  (hidden comment: GRM155R60J274KE01D)
C39  ValueDisplayed: 0.22µF  [0402S]  (hidden comment: GRM155R60J224KE01D)
C40  ValueDisplayed: 0.22µF  [0402S]  (hidden comment: GRM155R60J224KE01D)
C41  ValueDisplayed: 4.7µF  [0603]  (hidden comment: GRM188R60J475KE19D)
C42  ValueDisplayed: 0.27µF  [0402]  (hidden comment: GRM155R60J274KE01D)
C43  ValueDisplayed: 1µF  [0402]  (hidden comment: GRM155R61A105KE15D)
C44  ValueDisplayed: 0.47µF  [0603S]  (hidden comment: GRM188R70J474KA01D)
C45  ValueDisplayed: 0.1µF  [0402S]  (hidden comment: GRM155R70J104KA01D)
C46  ValueDisplayed: 10µF  [0402]  (hidden comment: CL05A106MQ5NUNC)
C47  ValueDisplayed: 0.1µF  [0402S]  (hidden comment: GRM155R70J104KA01D)
C48  ValueDisplayed: 10µF  [0402]  (hidden comment: CL05A106MQ5NUNC)
C49  ValueDisplayed: 0.1µF  [0402S]  (hidden comment: GRM155R70J104KA01D)
C50  ValueDisplayed: 10µF  [0402]  (hidden comment: CL05A106MQ5NUNC)
C51  ValueDisplayed: 3.3µF  [0603]  (hidden comment: GRM188R61A335KE15D)
C52  ValueDisplayed: 0.1µF  [0402]  (hidden comment: GRM155R61A104KA01D)
C53  ValueDisplayed: 2200pF  [0402]  (hidden comment: GRM155R70J222KA01D)
J3  ED555/2DS  [TERM_BLK_ED555-2DS]
R28  value 10.0  [0603]  (hidden comment: CRCW060310R0FKEA)
R29  value 10.0  [0603]  (hidden comment: CRCW060310R0FKEA)
R30  value 2.00Meg  [0402]  (hidden comment: CRCW04022M00FKED)
R31  value 3.24k  [1206]  (hidden comment: PFC-W1206R-12-3241-B)
R32  value 1.00k  [0402]  (hidden comment: CRCW04021K00FKED)
R33  value 47  [0402]  (hidden comment: CRCW040247R0JNED)
R34  value 47  [0402]  (hidden comment: CRCW040247R0JNED)
R35  value 47  [0402]  (hidden comment: CRCW040247R0JNED)
R36  value 1.00k  [0402]  (hidden comment: CRCW04021K00FKED)
R37  value 2.00Meg  [0402]  (hidden comment: CRCW04022M00FKED)
R38  value 10.0  [0603]  (hidden comment: CRCW060310R0FKEA)
R39  value 10.0  [0603]  (hidden comment: CRCW060310R0FKEA)
R40  value 10.0  [0603]  (hidden comment: CRCW060310R0FKEA)
R41  value 1.0Meg  [0402]  (hidden comment: CRCW04021M00JNED)
R42  value 10.0  [0603]  (hidden comment: CRCW060310R0FKEA)
R43  value 47k  [0402]  (hidden comment: CRCW040247K0JNED)
R44  value 2.00k  [0402S]  (hidden comment: CRCW04022K00FKED)
S1  SKRKAEE010  [SW_SKRKAEE010]
TC1  value 100 Ohm  [1206]  (hidden comment: PTS120601B100RP100)
U6  ADS1220IRVA  [RVA0016A]
U7  MSP430F5172IRSB  [RSB0040B]
U8  SN74LVC125ARGY  [RGY0014A]

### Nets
isoGND: C37.1 C38.1 C39.2 C40.2 C42.2 C44.2 C45.2 C46.2 C47.2 C48.2 C49.2 C50.2 C51.2 C52.2 C53.2 R31.2 R37.1 S1.1 U6.1(CLK) U6.2(DGND) U6.3(AVSS) U6.6(REFN0) U6.17(PAD) U7.18(DVSS) U7.26(DVSS) U7.40(AVSS) U7.41(PAD) U8.2(1A) U8.4(2~{OE}) U8.7(GND) U8.10(3~{OE}) U8.15(PAD) ; off-sheet REFN0  [also labelled REFN0]
AIN0: C38.2 C41.1 R32.2 U6.9(AIN0/REFP1) ; off-sheet AIN0
AIN1: C41.2 C42.1 R36.2 U6.8(AIN1) ; off-sheet AIN1
AIN2: C37.2 C43.1 R31.1 TC1.2 U6.5(AIN2) U6.7(REFP0) ; off-sheet REFP0, off-sheet AIN2  [also labelled REFP0]
AIN3: C43.2 TC1.1 U6.4(AIN3/REFN1) ; off-sheet AIN3
BSL_Rx: U7.35(P3.6/PM_TA0.1/A7/VEREF-/CB11) ; off-sheet BSL_Rx
BSL_Tx: U7.36(P3.7/PM_TA0.0/A6/CB10) ; off-sheet BSL_Tx
DIN_ADC: R35.2 U7.3(P1.2/PM_UCA0RXD/PM_UCA0SOMI/A2/CB2) ; off-sheet DIN_ADC
DOUT_ADC: U6.13(DOUT/~{DRDY}) U7.4(P1.3/PM_UCB0CLK/PM_UCA0STE/A3/CB3) ; off-sheet DOUT_ADC
iso1: U8.5(2A) ; off-sheet iso1
iso2: U8.3(1Y) ; off-sheet iso2
iso3: U8.8(3Y) ; off-sheet iso3
iso3V3: R28.2 R29.2 R30.2 R38.2 R39.2 R40.2 R41.2 R42.1 R43.2 ; off-sheet iso3V3
iso_Rx: R44.2 U7.12(P1.7/PM_TD0.1) U8.9(3A) U8.11(4Y) ; off-sheet iso_Rx
iso_Tx: U7.13(P2.0/PM_TD0.2) U8.12(4A) ; off-sheet iso_Tx
n_iso_Tx_EN: U7.14(P2.1/PM_TD1.0) U8.1(1~{OE}) U8.13(4~{OE}) ; off-sheet n_iso_Tx_EN
nCS_ADC: R33.2 U7.1(P1.0/PM_UCA0CLK/PM_UCB0STE/A0/CB0) ; off-sheet nCS_ADC
nDRDY_ADC: U6.12(~{DRDY}) U7.5(P1.4/PM_UCB0SIMO/PM_UCB0SDA/A4/CB4) ; off-sheet nDRDY_ADC
SBWTCK: U7.32(TEST/SBWTCK) ; off-sheet SBWTCK
SBWTDIO: C53.1 R43.1 U7.33(~{RST}/NMI/SBWTDIO) ; off-sheet SBWTDIO
SCLK_ADC: R34.2 U7.2(P1.1/PM_UCA0TXD/PM_UCA0SIMO/A1/CB1) ; off-sheet SCLK_ADC
SW1: R41.1 S1.2 U7.20(P2.5/PM_TEC0FLT0/PM_TD0.1)
SW2: U7.21(P2.6/PM_TEC0FLT1/PM_TD0.2) ; off-sheet SW2
NetC39_1: C39.1 R28.1 U6.11(DVDD)
NetC40_1: C40.1 R29.1 U6.10(AVDD)
NetC44_1: C44.1 U7.25(VCORE)
NetC45_1: C45.1 C46.1 R38.1 U7.37(AVCC)
NetC47_1: C47.1 C48.1 R39.1 U7.27(DVCC)
NetC49_1: C49.1 C50.1 R40.1 U7.17(DVIO)
NetC51_1: C51.1 C52.1 R42.2 U8.14(VCC)
NetJ3_1: J3.1 R30.1 R36.1 R37.2
NetJ3_2: J3.2 R32.1
NetR33_1: R33.1 U6.16(~{CS})
NetR34_1: R34.1 U6.15(SCLK)
NetR35_1: R35.1 U6.14(DIN)
NetR44_1: R44.1 U8.6(2Y)

Not connected (* = marked no-connect by the designer): U7 6(P1.5/PM_UCB0SOMI/PM_UCB0SCL/A5/CB5) 7(PJ.0/SMCLK/TDO/CB6) 8(PJ.1/MCLK/TDI/TCLK/CB7) 9(PJ.2/ADC10CLK/TMS/CB8) 10(PJ.3/ACLK/TCK/CB9) 11(P1.6/PM_TD0.0) 15(P2.2/PM_TD1.1) 16(P2.3/PM_TD1.2) 19(P2.4/PM_TEC0CLR/PM_TEC0FLT2/PM_TD0.0) 22(P2.7/PM_TEC1CLR/PM_TEC1FLT1/PM_TD1.0) 23(P3.0/PM_TEC1FLT2/PM_TD1.1) 24(P3.1/PM_TEC1FLT0/PM_TD1.2) 28(PJ.6/TD1CLK/TD0.1/CB15) 29(P3.2/PM_TD0.0/PM_SMCLK/CB14) 30(P3.3/PM_TA0CLK/PM_CBOUT/CB13) 31(P3.4/PM_TD0CLK/PM_MCLK) 34(P3.5/PM_TA0.2/A8/_VEREF+/CB12) 38(PJ.4/XOUT) 39(PJ.5/XIN)

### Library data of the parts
C37 C43 = GRM155R61A105KE15D: as C23 on sheet TIDA-00189_E2_PWR
C38 C42 = GRM155R60J274KE01D: CAP, CERM, 0.27uF, 6.3V, +/-10%, X5R, 0402; Manufacturer: MuRata; Polarized: N; CompType: Capacitor; U/M: EA; Cap_F: 0.00000027; Tolerance_%: 10; Value1: Unknown; VDC_V: 6.3; TaMin_C: -55; TaMax_C: 85
C39 C40 = GRM155R60J224KE01D: CAP, CERM, 0.22uF, 6.3V, +/-10%, X5R, 0402; Manufacturer: MuRata; Polarized: N; CompType: Capacitor; U/M: EA; Cap_F: 0.00000022; Tolerance_%: 10; Value1: Unknown; VDC_V: 6.3; TaMin_C: -55; TaMax_C: 85; Cap_Case: 0402
C41 = GRM188R60J475KE19D: CAP, CERM, 4.7uF, 6.3V, +/-10%, X5R, 0603; Manufacturer: MuRata; Polarized: N; CompType: Capacitor; U/M: EA; Cap_F: 0.0000047; Tolerance_%: 10; ESR_Ohm: 0.005; Value1: 0.005 ohm; VDC_V: 6.3; IRMS_A: 2; TaMin_C: -55; TaMax_C: 85
C44 = GRM188R70J474KA01D: CAP, CERM, 0.47uF, 6.3V, +/-10%, X7R, 0603; Manufacturer: MuRata; Polarized: N; CompType: Capacitor; U/M: EA; Cap_F: 0.00000047; Tolerance_%: 10; Value1: Unknown; VDC_V: 6.3; TaMin_C: -55; TaMax_C: 125; Cap_Case: 0603
C45 C47 C49 = GRM155R70J104KA01D: CAP, CERM, 0.1uF, 6.3V, +/-10%, X7R, 0402; Manufacturer: MuRata; Polarized: N; CompType: Capacitor; U/M: EA; Cap_F: 0.0000001; Tolerance_%: 10; Value1: Unknown; VDC_V: 6.3; TaMin_C: -55; TaMax_C: 125; Cap_Case: 0402
C46 C48 C50 = CL05A106MQ5NUNC: CAP, CERM, 10uF, 6.3V, +/-20%, X5R, 0402; Manufacturer: Samsung; Polarized: N; CompType: Capacitor; U/M: EA; Cap_F: 0.00001; Tolerance_%: 20; Value1: Unknown; VDC_V: 6.3; TaMin_C: -55; TaMax_C: 85
C51 = GRM188R61A335KE15D: CAP, CERM, 3.3uF, 10V, +/-10%, X5R, 0603; Manufacturer: MuRata; Polarized: N; CompType: Capacitor; U/M: EA; Cap_F: 0.0000033; Tolerance_%: 10; ESR_Ohm: 0.005; Value1: 0.005 ohm; IRMS_A: 1.7; TaMin_C: -55; TaMax_C: 85
C52 = GRM155R61A104KA01D: as C11 on sheet TIDA-00189_E2_PWR
C53 = GRM155R70J222KA01D: as C34 on sheet TIDA-00189_E2_DAC
J3 = ED555/2DS: as J1 on sheet TIDA-00189_E2_PWR
R28 R29 R38-R40 R42 = CRCW060310R0FKEA: as R15 on sheet TIDA-00189_E2_PWR
R30 R37 = CRCW04022M00FKED: RES, 2.00Meg ohm, 1%, 0.063W, 0402; Manufacturer: Vishay-Dale; CompType: Resistor; Res_ohm: 2000000; Value_Code: 2M00; Tolerance_%: 1; Power_W: 0.063; VDC_V: 50; TempCo: 100 ppm/C; EIA_Code: E96; U/M: EA
R31 = PFC-W1206R-12-3241-B: RES, 3.24k ohm, 0.1%, 0.333W, 1206; Manufacturer: TT Electronics/IRC; CompType: Resistor; Res_ohm: 3240; Value_Code: 3k24; Tolerance_%: 0.1; Power_W: 0.333; TempCo: 10 ppm/C; EIA_Code: E192; U/M: EA
R32 R36 = CRCW04021K00FKED: RES, 1.00k ohm, 1%, 0.063W, 0402; Manufacturer: Vishay-Dale; CompType: Resistor; Res_ohm: 1000; Value_Code: 1k00; Tolerance_%: 1; Power_W: 0.063; VDC_V: 50; TempCo: 100 ppm/C; EIA_Code: E96; U/M: EA
R33-R35 = CRCW040247R0JNED: RES, 47 ohm, 5%, 0.063W, 0402; Manufacturer: Vishay-Dale; CompType: Resistor; Value_Code: 47R0; Tolerance_%: 5; Power_W: 0.063; VDC_V: 50; TempCo: 200 ppm/C; EIA_Code: E24; U/M: EA
R41 = CRCW04021M00JNED: RES, 1.0Meg ohm, 5%, 0.063W, 0402; Manufacturer: Vishay-Dale; CompType: Resistor; Res_ohm: 1000000; Value_Code: 1M00; Tolerance_%: 5; Power_W: 0.063; VDC_V: 50; TempCo: 200 ppm/C; EIA_Code: E24; U/M: EA
R43 = CRCW040247K0JNED: RES, 47k ohm, 5%, 0.063W, 0402; Manufacturer: Vishay-Dale; CompType: Resistor; Res_ohm: 47000; Value_Code: 47k0; Tolerance_%: 5; Power_W: 0.063; VDC_V: 50; TempCo: 200 ppm/C; EIA_Code: E24; U/M: EA
R44 = CRCW04022K00FKED: RES, 2.00k ohm, 1%, 0.063W, 0402; Manufacturer: Vishay-Dale; CompType: Resistor; Res_ohm: 2000; Value_Code: 2k00; Tolerance_%: 1; Power_W: 0.063; VDC_V: 50; TempCo: 100 ppm/C; EIA_Code: E96; U/M: EA
S1 = SKRKAEE010: Switch, Push Button, SMD; Manufacturer: Alps; SymbolCreator: a0412235; Circuit: SPST-NO; VDC_V: 12; SwitchFunction: Off-Mom; PositionCount: 1; CurrentRating_mA: 50
TC1 = PTS120601B100RP100: Temperature Sensor, 100 ohm, 1%, 1206; Manufacturer: Vishay/Beyschlag; CompType: Thermistor
U6 = ADS1220IRVA: Low-Power, Low-Noise, 24-Bit Analog-to-Digital Converter for Small Signal Sensors, RVA0016A; Alternate Manufacturer: None; Manufacturer: Texas Instruments; SymbolCreator: x0208326; CompType: IC; U/M: EA
U7 = MSP430F5172IRSB: Mixed Signal Microcontroller, RSB0040B; Alternate Manufacturer: None; Manufacturer: Texas Instruments; SymbolCreator: a0411947; CompType: IC; U/M: EA
U8 = SN74LVC125ARGY: QUADRUPLE BUS BUFFER GATE WITH 3-STATE OUTPUTS,  RGY0014A; Alternate Manufacturer: None; Manufacturer: Texas Instruments; SymbolCreator: a0412235; CompType: IC; U/M: EA

## Sheet TIDA-00189_E2_Periph.SchDoc
size 431 x 279 mm; Date: Not shown in title block; ApprovedBy: Not shown in title block; CheckedBy: Not shown in title block; Author: Not shown in title block; CompanyName: Not shown in title block; Engineer: Not shown in title block; Organization: Not shown in title block; Address1: Not shown in title block; Address2: Not shown in title block; Address3: Not shown in title block; Address4: Not shown in title block; DocumentNumber: 6; Revision: Use project parameter SCH_Rev; SheetNumber: 6; SheetTotal: 6; PageSetup: Record=PageOptions¦CenterHorizontal=True¦CenterVertical=True¦PrintScale=0.94¦XCorrection=1.00¦YCorrection=1.00¦PrintKind=0¦BorderSize=5000000¦LeftOffset=0¦BottomOffset=0¦Orientation=2¦PaperLength=4200¦PaperWidth=2970¦Scale=100¦PaperSource=7¦PrintQuality=600¦MediaType=1¦DitherType=10¦PaperKind=A3¦PrintScaleMode=1
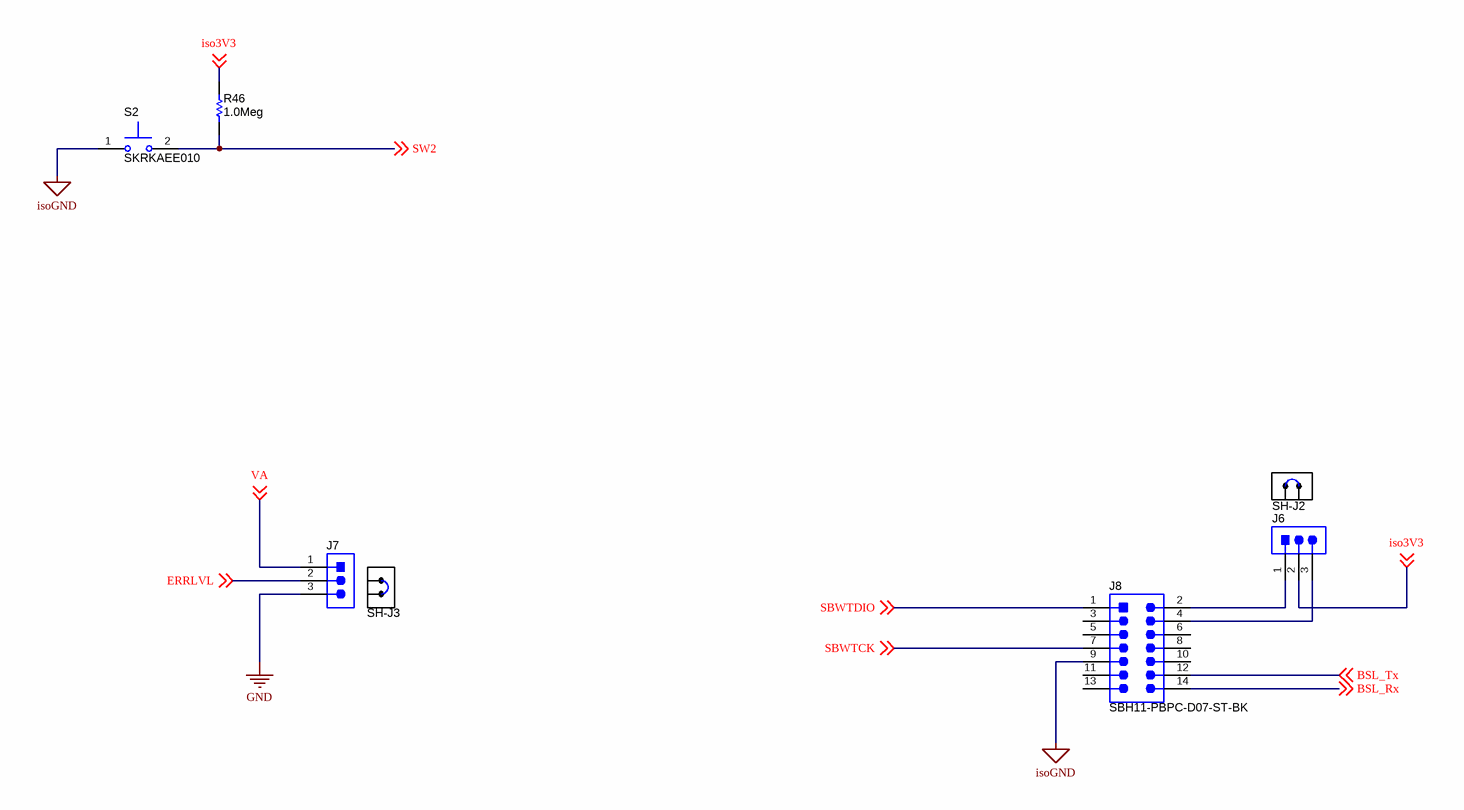
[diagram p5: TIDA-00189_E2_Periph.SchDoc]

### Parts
J6  PEC03SAAN  [CONN_PEC03SAAN]  (value not drawn)
J7  PEC03SAAN  [CONN_PEC03SAAN]  (value not drawn)
J8  SBH11-PBPC-D07-ST-BK  [CONN_SBH11-PBPC-D07-ST-BK]
R46  value 1.0Meg  [0402]  (hidden comment: CRCW04021M00JNED)
S2  SKRKAEE010  [SW_SKRKAEE010]
SH-J2  969102-0000-DA  [SNT-100-BK-G]  (value not drawn)
SH-J3  969102-0000-DA  [SNT-100-BK-G]  (value not drawn)

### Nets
GND: J7.3
isoGND: J8.9 S2.1
BSL_Rx: J8.14 ; off-sheet BSL_Rx
BSL_Tx: J8.12 ; off-sheet BSL_Tx
ERRLVL: J7.2 ; off-sheet ERRLVL
iso3V3: J6.2 R46.2 ; off-sheet iso3V3
SBWTCK: J8.7 ; off-sheet SBWTCK
SBWTDIO: J8.1 ; off-sheet SBWTDIO
SW2: R46.1 S2.2 ; off-sheet SW2
VA: J7.1 ; off-sheet VA
NetJ6_1: J6.1 J8.2
NetJ6_3: J6.3 J8.4

Not connected (* = marked no-connect by the designer): J8 3 5 6 8 10 11 13

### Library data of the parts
J6 J7 = PEC03SAAN: Header, 100mil, 3x1, Tin plated, TH; Manufacturer: Sullins Connector Solutions; SymbolCreator: a0799628; U/M: EA
J8 = SBH11-PBPC-D07-ST-BK: Header (shrouded), 100 mil, 7x2, Gold plated, TH; Manufacturer: Sullins Connector Solutions; SymbolCreator: a0412235; CompType: Connector; U/M: EA
R46 = CRCW04021M00JNED: as R41 on sheet TIDA-00189_E2_AFE_MCU
S2 = SKRKAEE010: as S1 on sheet TIDA-00189_E2_AFE_MCU
SH-J2 SH-J3 = 969102-0000-DA: Shunt, 100mil, Gold plated, Black; Manufacturer: 3M; Alternate Manufacturer: Samtec; Value: 1x2; Note: You can "mate" this to a header by matching the designator.  i.e. use SH-J3 for header J3

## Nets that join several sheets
3V3: TIDA-00189_E2_PWR (C22.1 TP9.1 U3.1), TIDA-00189_E2_DAC (R21.2 R22.2)
GND: TIDA-00189_E2_PWR (13 pins), TIDA-00189_E2_DAC (11 pins), TIDA-00189_E2_Periph (J7.3)
isoGND: TIDA-00189_E2_PWR (8 pins), TIDA-00189_E2_AFE_MCU (32 pins), TIDA-00189_E2_Periph (J8.9 S2.1)
BSL_Rx: TIDA-00189_E2_AFE_MCU (U7.35), TIDA-00189_E2_Periph (J8.14)
BSL_Tx: TIDA-00189_E2_AFE_MCU (U7.36), TIDA-00189_E2_Periph (J8.12)
ERRLVL: TIDA-00189_E2_DAC (U5.8), TIDA-00189_E2_Periph (J7.2)
iso1: TIDA-00189_E2_DAC (C30.1 T3.6), TIDA-00189_E2_AFE_MCU (U8.5)
iso2: TIDA-00189_E2_DAC (R24.1), TIDA-00189_E2_AFE_MCU (U8.3)
iso3: TIDA-00189_E2_DAC (T3.4), TIDA-00189_E2_AFE_MCU (U8.8)
iso3V3: TIDA-00189_E2_PWR (C23.1 TP10.1 U4.1), TIDA-00189_E2_AFE_MCU (9 pins), TIDA-00189_E2_Periph (J6.2 R46.2)
LOOP_M: TIDA-00189_E2_PWR (D4.2 D5.2), TIDA-00189_E2_DAC (C31.2 C32.2 R26.2)
LOOP_P: TIDA-00189_E2_PWR (D1.1 D2.1 R1.1), TIDA-00189_E2_DAC (R23.2)
SBWTCK: TIDA-00189_E2_AFE_MCU (U7.32), TIDA-00189_E2_Periph (J8.7)
SBWTDIO: TIDA-00189_E2_AFE_MCU (C53.1 R43.1 U7.33), TIDA-00189_E2_Periph (J8.1)
SW2: TIDA-00189_E2_AFE_MCU (U7.21), TIDA-00189_E2_Periph (R46.1 S2.2)
VA: TIDA-00189_E2_DAC (C29.1 R22.1 U5.15), TIDA-00189_E2_Periph (J7.1)

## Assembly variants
TIDA-00189_E2: not fitted C2 C3 C4 C8 C9 C18 FID1 FID2 FID3 FID4 FID5 FID6 R2 R5 R6 R7 R9 R14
